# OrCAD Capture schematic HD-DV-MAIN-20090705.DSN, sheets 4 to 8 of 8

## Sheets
4 CONNECTOR: size B
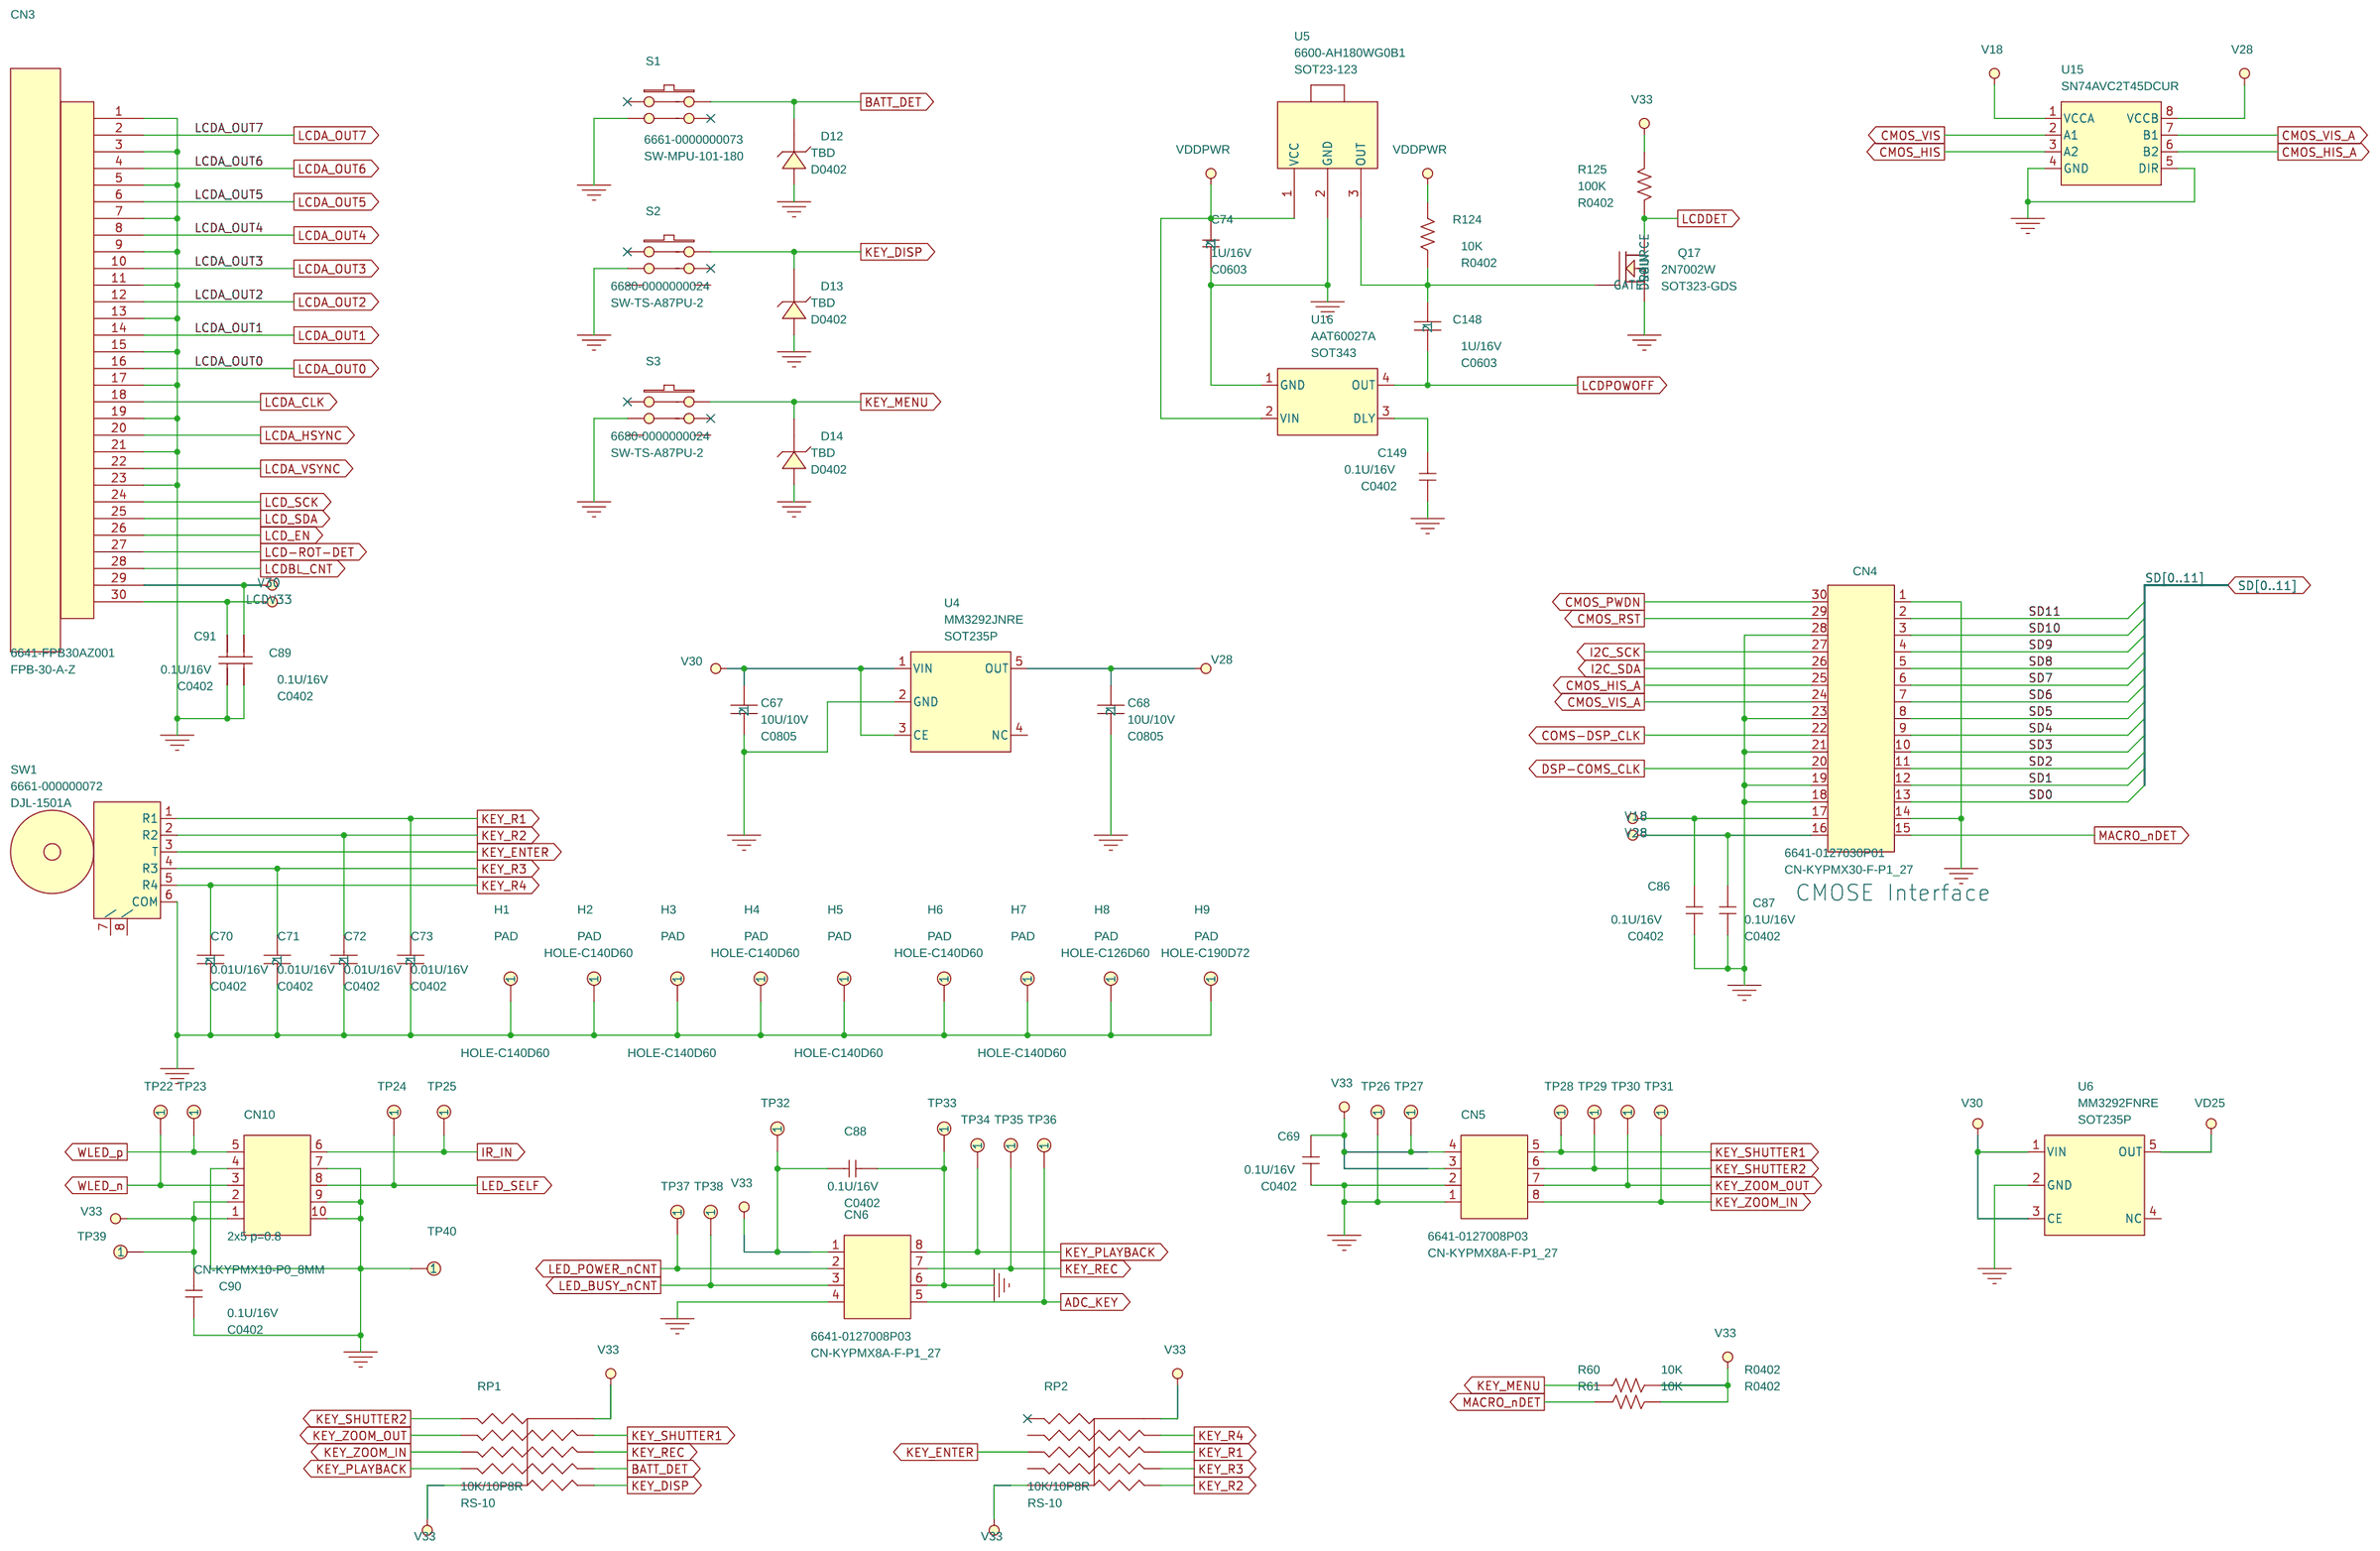
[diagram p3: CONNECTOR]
5 DDR2 SDRAM: size A4
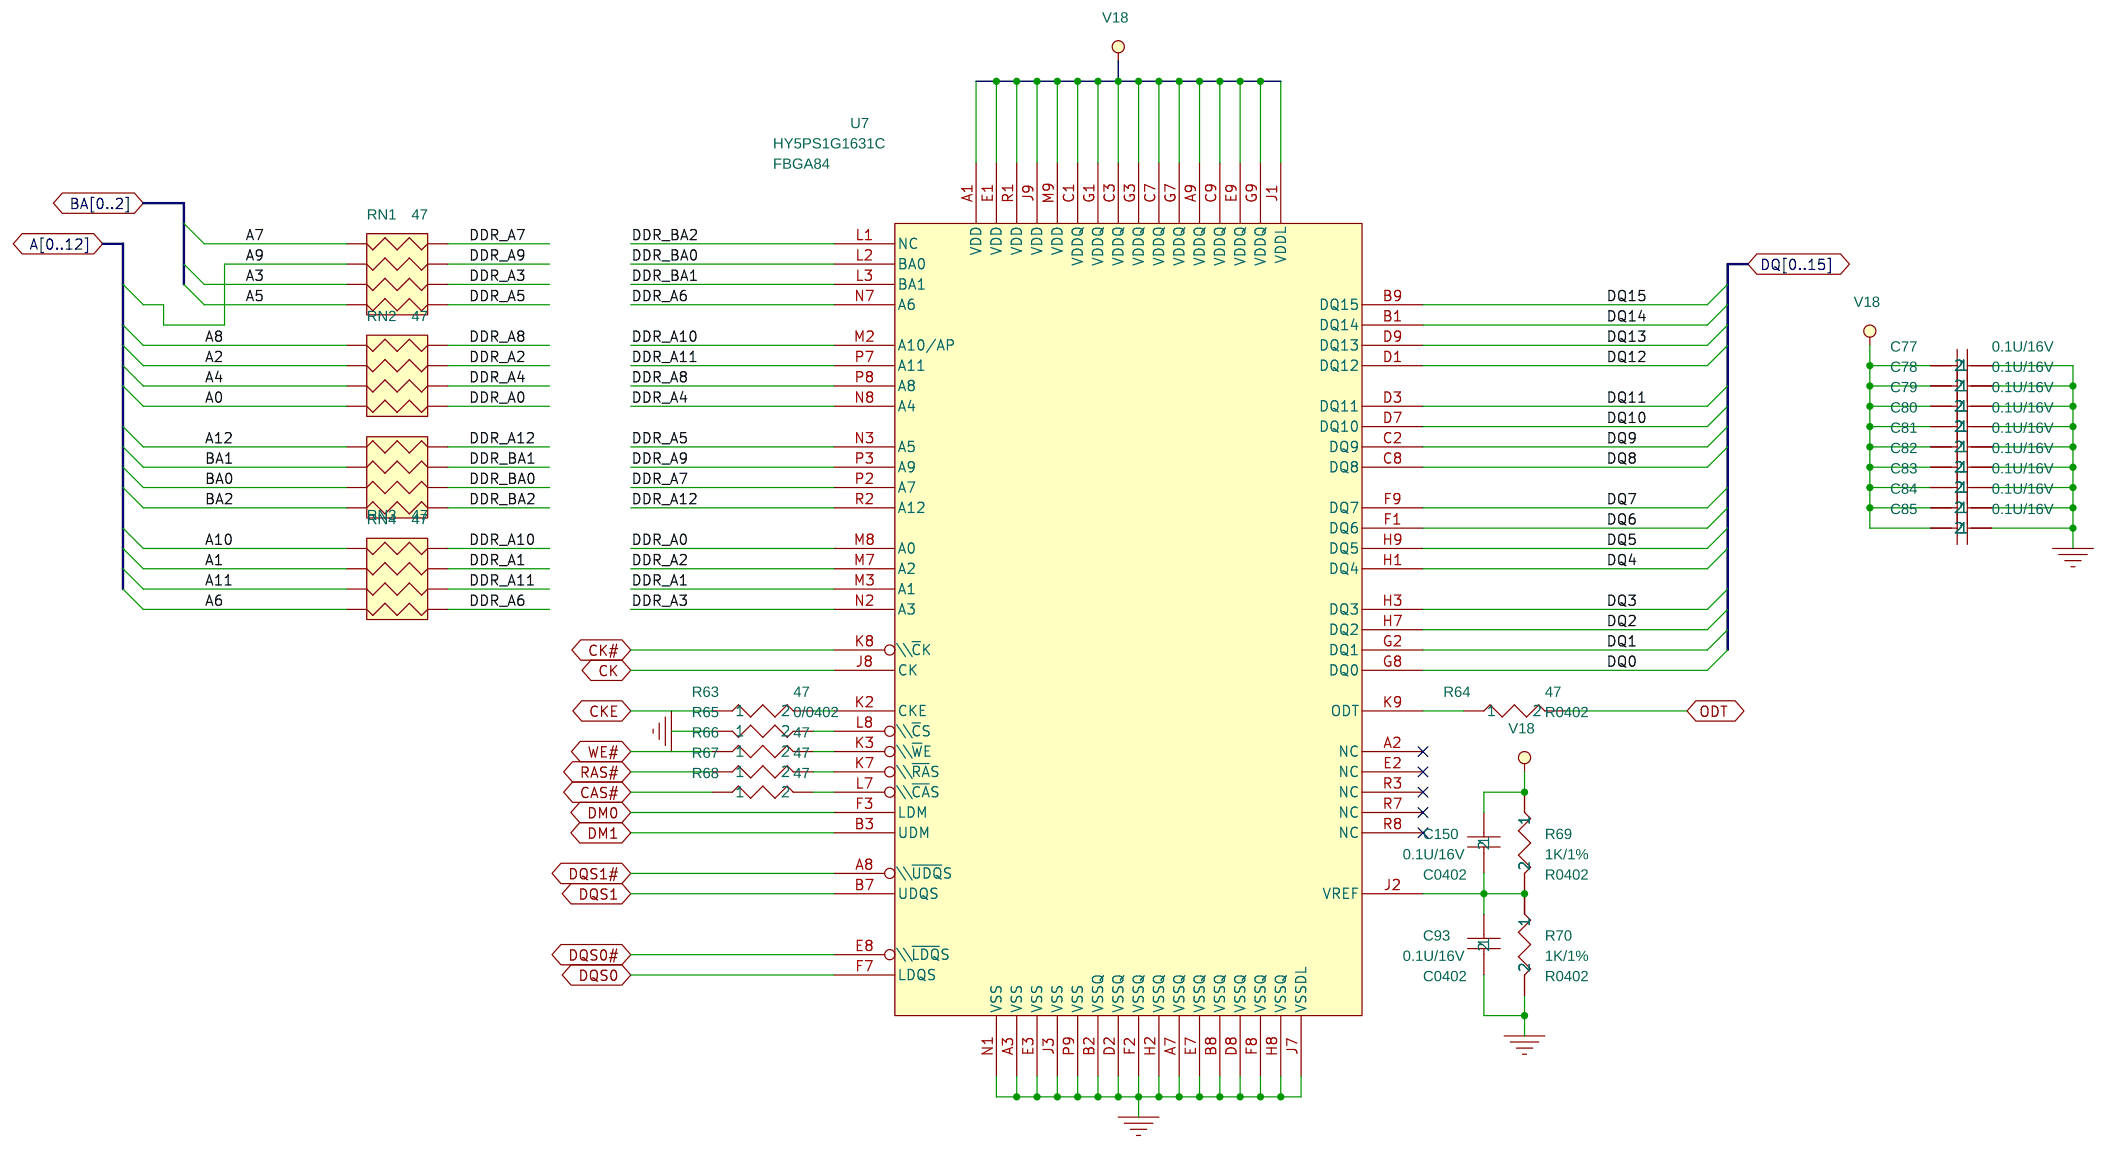
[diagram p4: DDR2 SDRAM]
6 NAND & SD: size A4
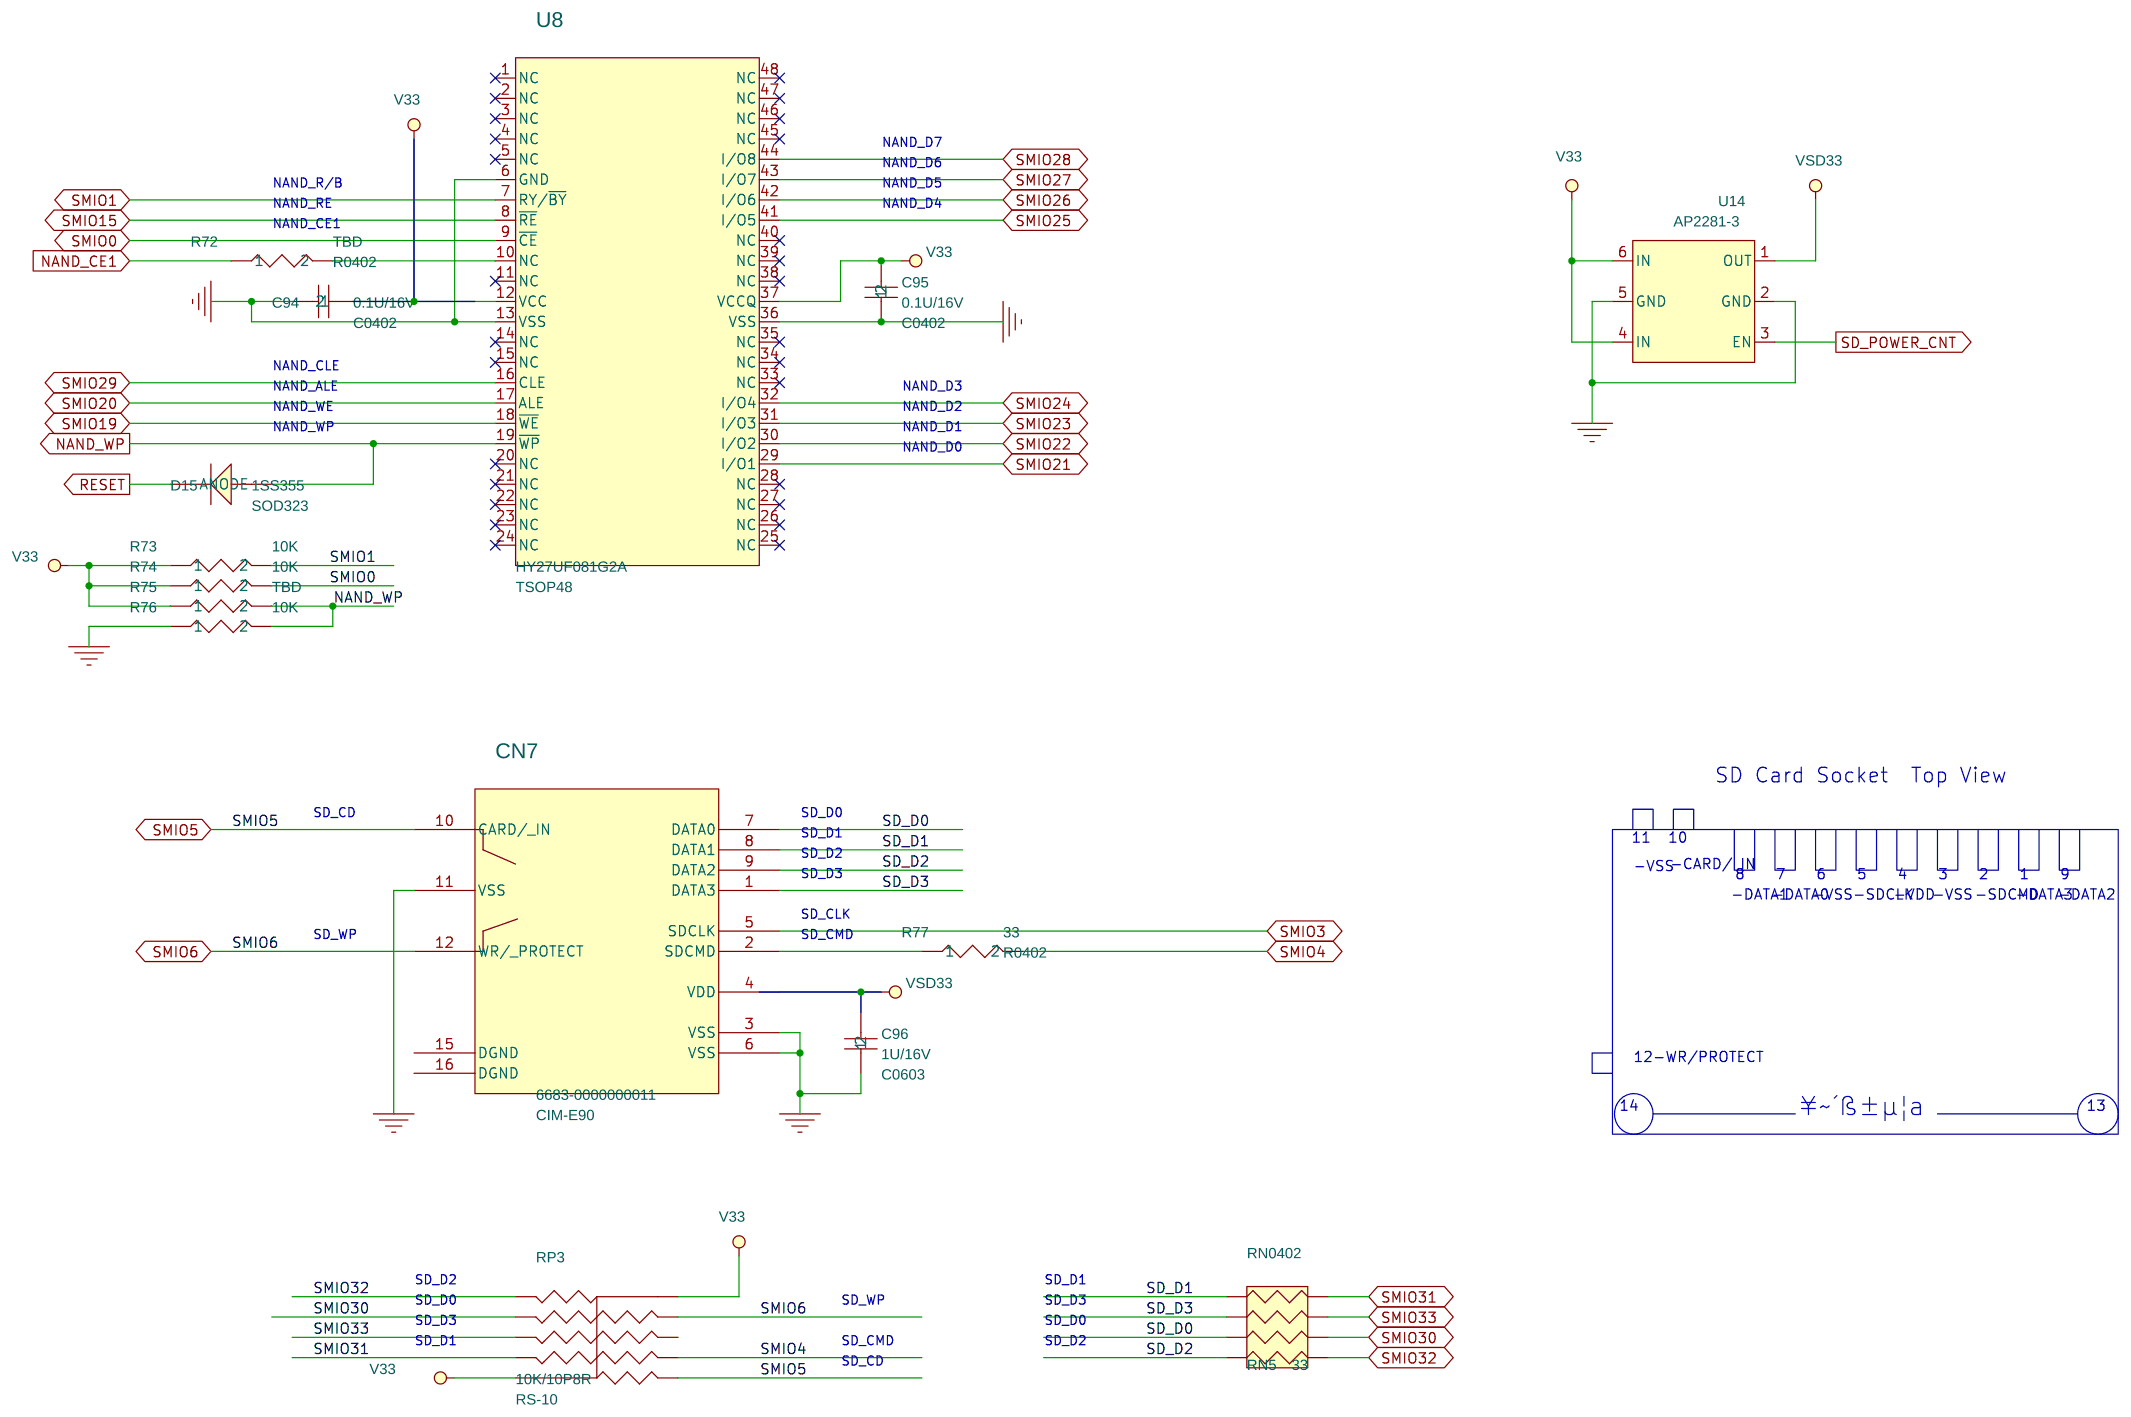
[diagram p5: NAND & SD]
7 POWER & ON & OFF: size B
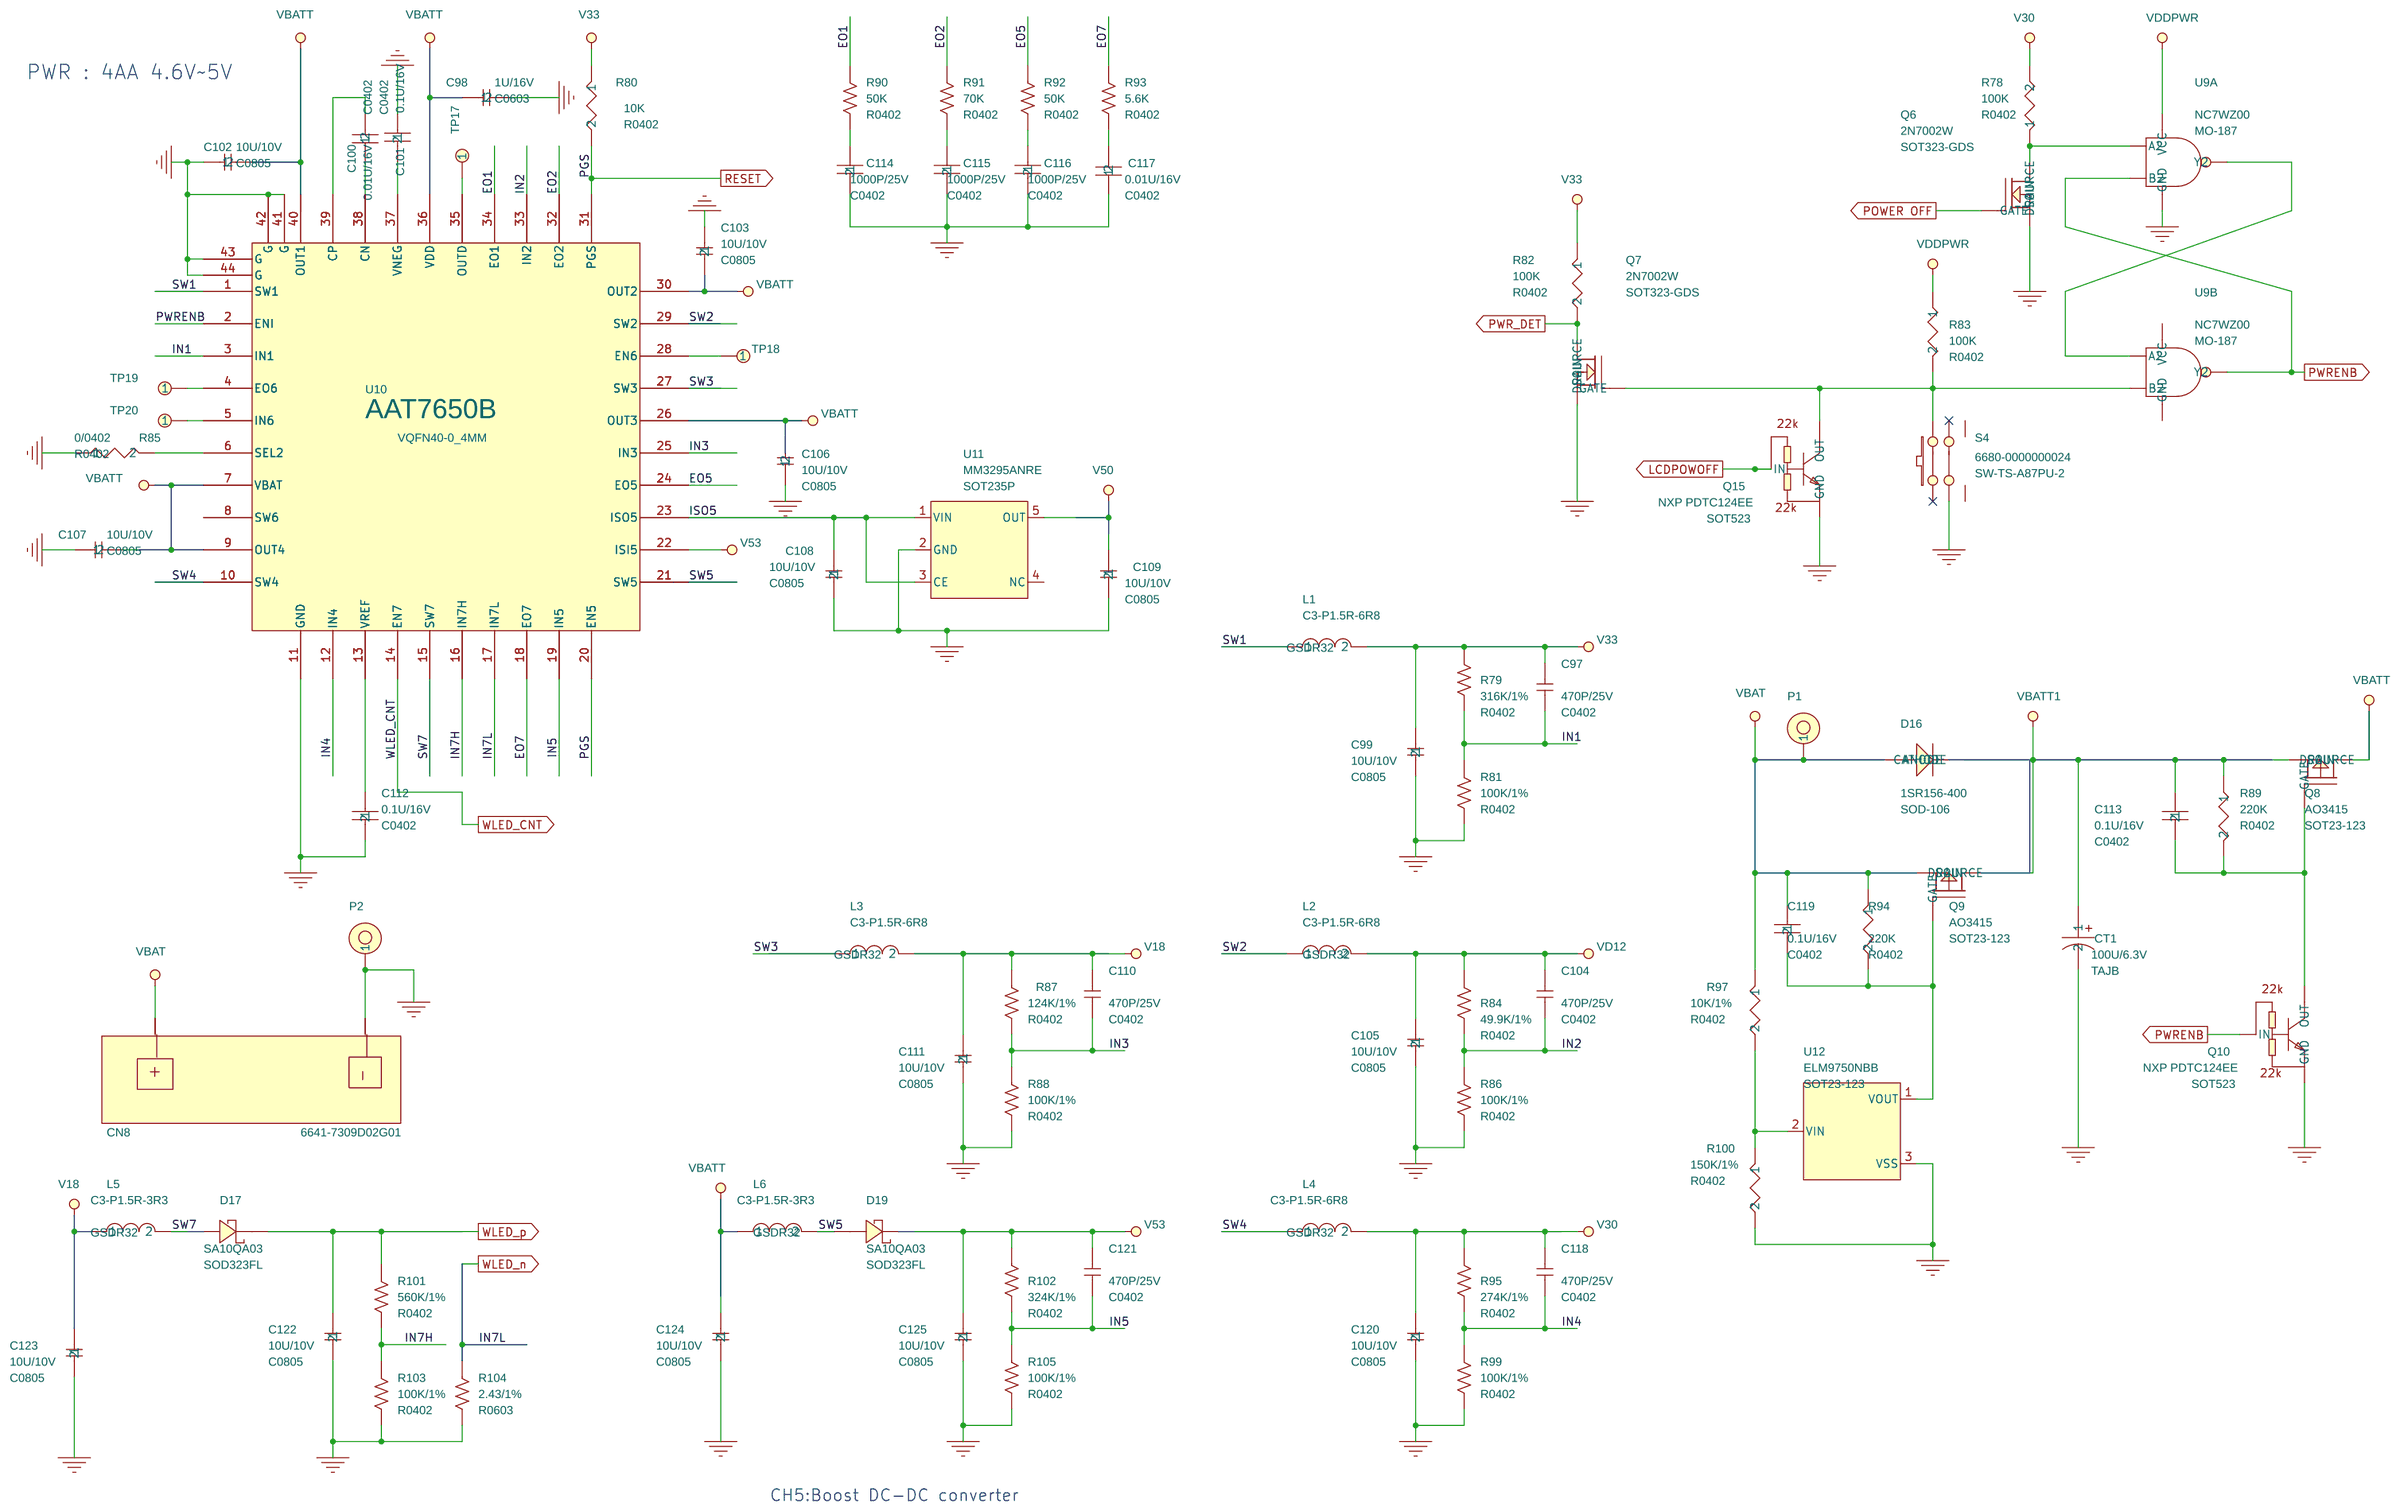
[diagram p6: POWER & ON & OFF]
8 WM8978 & USB CON: size B
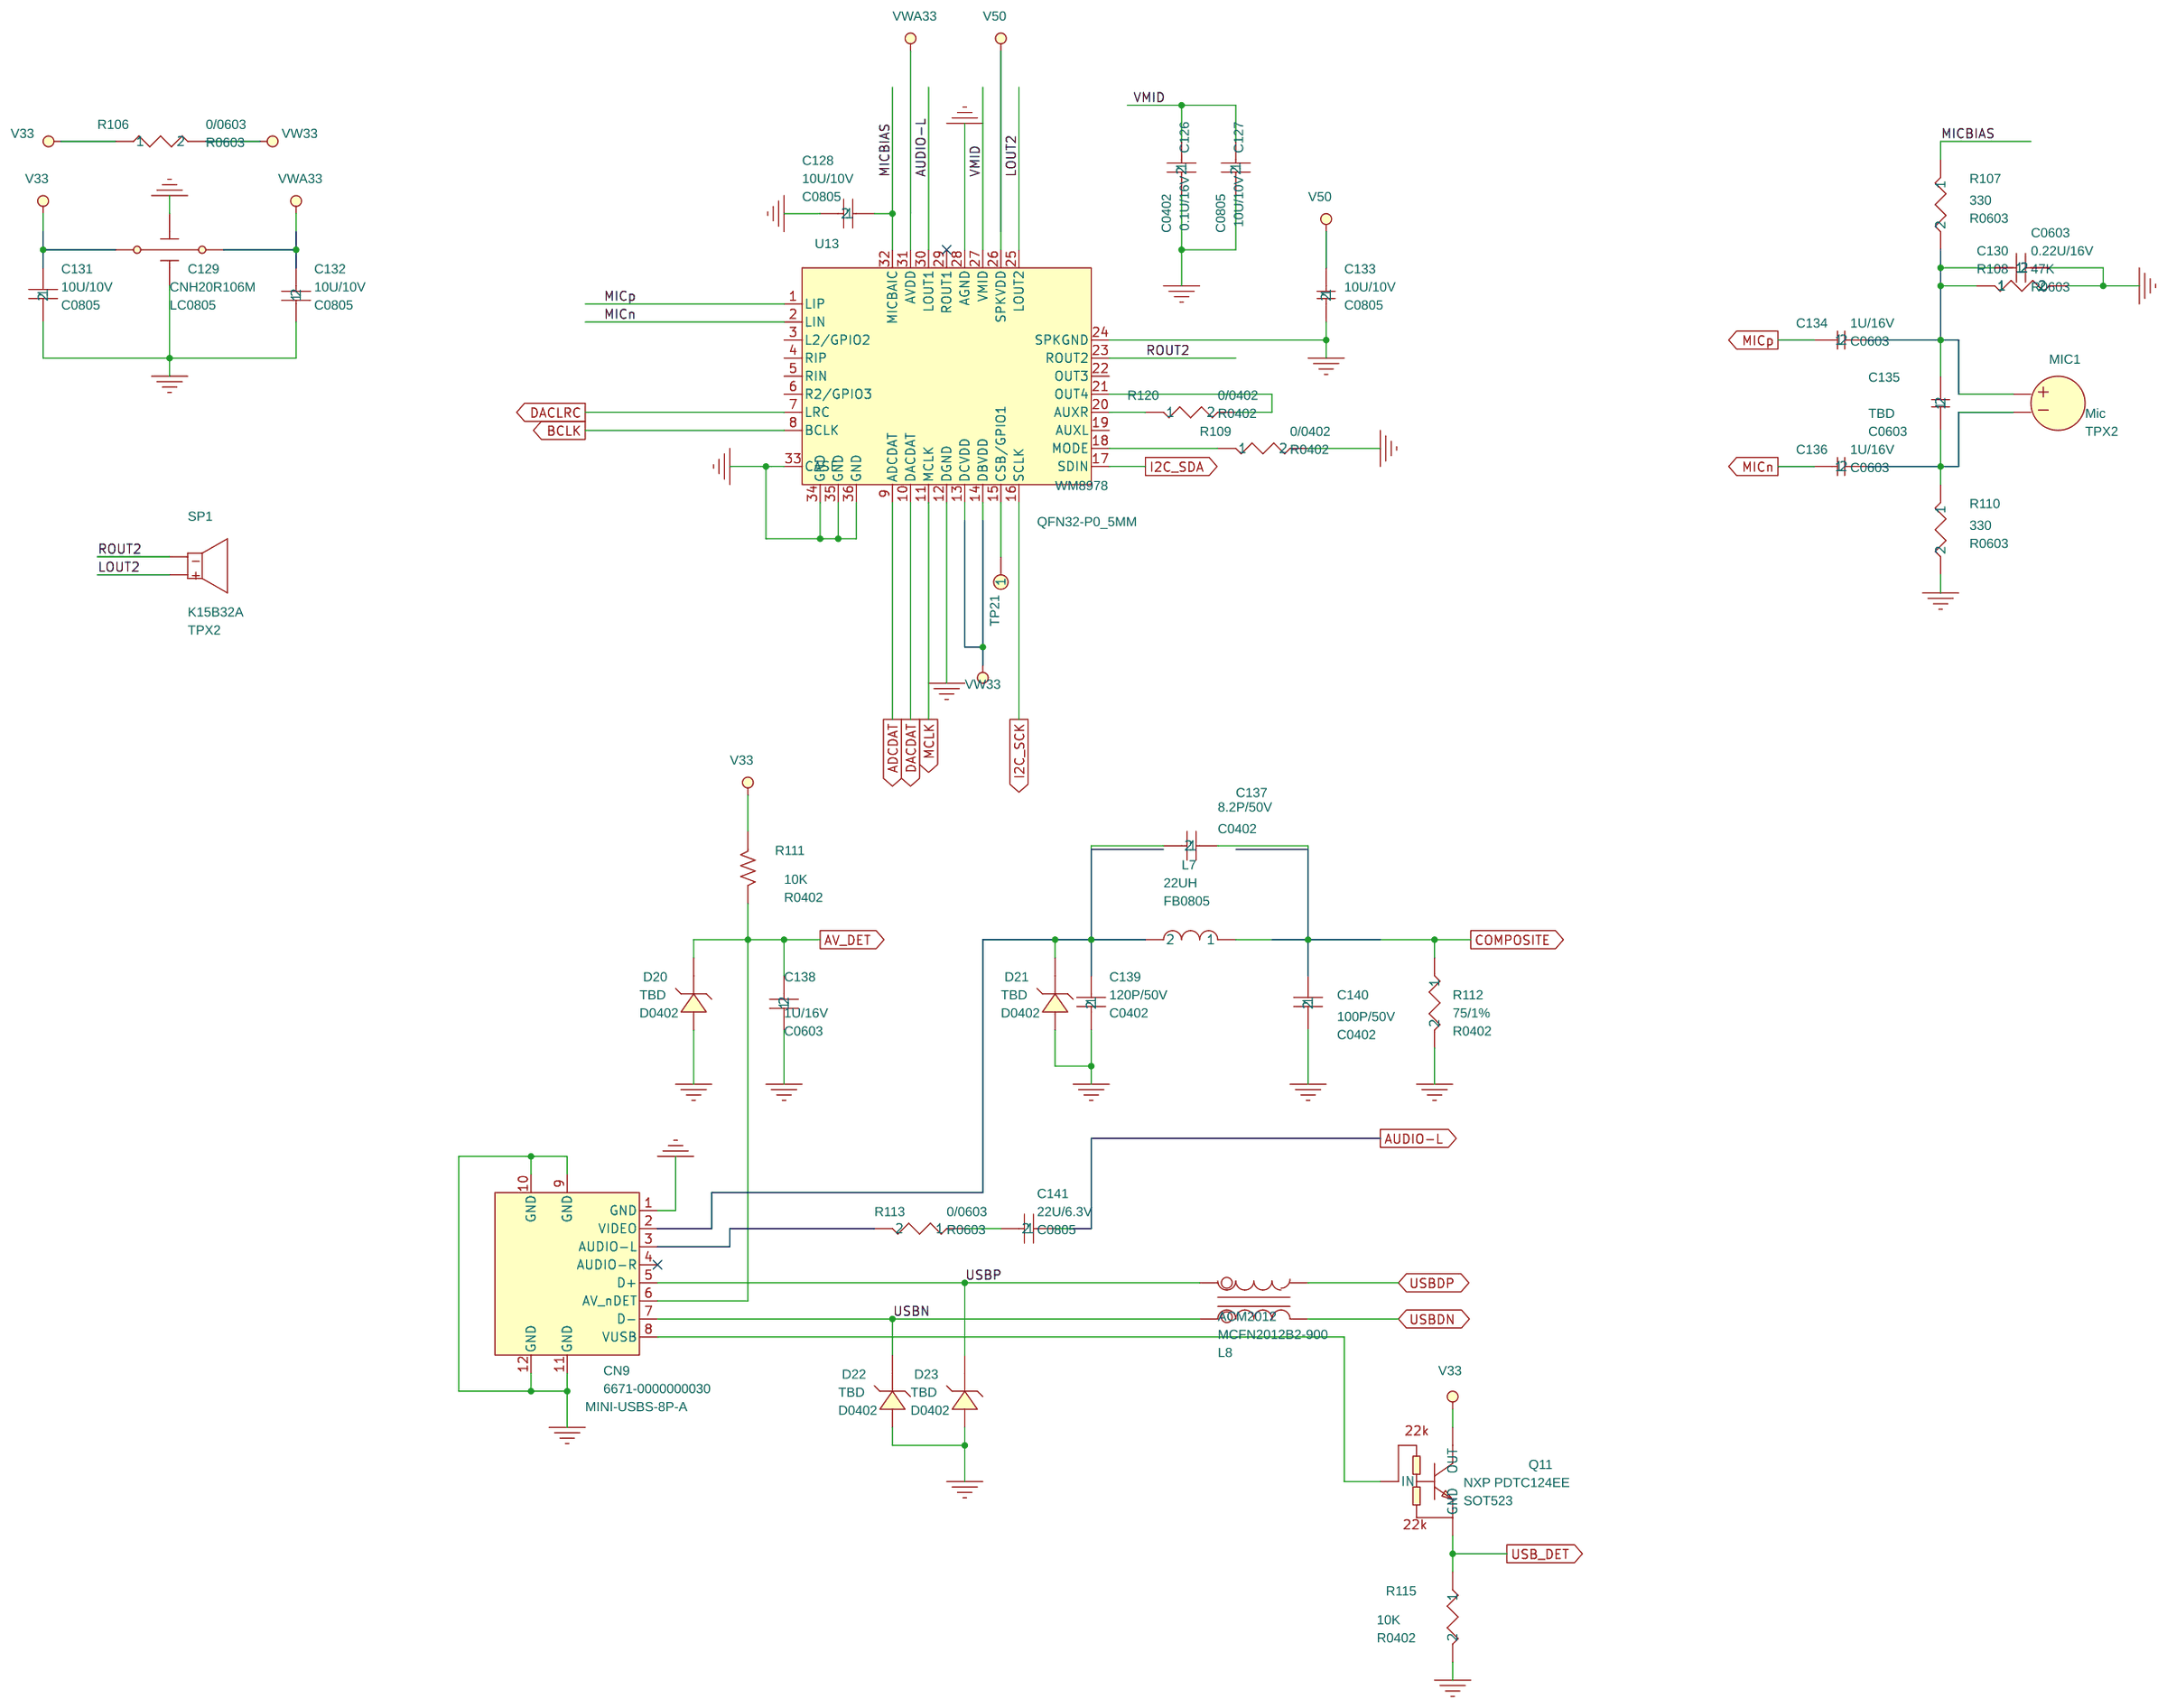
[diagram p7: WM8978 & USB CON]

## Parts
sheet CONNECTOR
C67  10U/10V  [C0805]
C68  10U/10V  [C0805]
C69  0.1U/16V  [C0402]
C70  0.01U/16V  [C0402]
C71  0.01U/16V  [C0402]
C72  0.01U/16V  [C0402]
C73  0.01U/16V  [C0402]
C74  1U/16V  [C0603]
C86  0.1U/16V  [C0402]
C87  0.1U/16V  [C0402]
C88  0.1U/16V  [C0402]
C89  0.1U/16V  [C0402]
C90  0.1U/16V  [C0402]
C91  0.1U/16V  [C0402]
C148  1U/16V  [C0603]
C149  0.1U/16V  [C0402]
CN3  6641-FPB30AZ001  [FPB-30-A-Z]
CN4  6641-0127030P01  [CN-KYPMX30-F-P1_27]
CN5  6641-0127008P03  [CN-KYPMX8A-F-P1_27]
CN6  6641-0127008P03  [CN-KYPMX8A-F-P1_27]
CN10  2x5 p=0.8  [CN-KYPMX10-P0_8MM]
D12  TBD  [D0402]
D13  TBD  [D0402]
D14  TBD  [D0402]
H1  PAD  [HOLE-C140D60]
H2  PAD  [HOLE-C140D60]
H3  PAD  [HOLE-C140D60]
H4  PAD  [HOLE-C140D60]
H5  PAD  [HOLE-C140D60]
H6  PAD  [HOLE-C140D60]
H7  PAD  [HOLE-C140D60]
H8  PAD  [HOLE-C126D60]
H9  PAD  [HOLE-C190D72]
Q17  2N7002W  [SOT323-GDS]
R60  10K  [R0402]
R61  10K  [R0402]
R124  10K  [R0402]
R125  100K  [R0402]
RP1  10K/10P8R  [RS-10]
RP2  10K/10P8R  [RS-10]
S1  6661-0000000073  [SW-MPU-101-180]
S2  6680-0000000024  [SW-TS-A87PU-2]
S3  6680-0000000024  [SW-TS-A87PU-2]
SW1  6661-000000072  [DJL-1501A]
TP22  TP  [TP40]
TP23  TP  [TP40]
TP24  TP  [TP40]
TP25  TP  [TP40]
TP26  TP  [TP40]
TP27  TP  [TP40]
TP28  TP  [TP40]
TP29  TP  [TP40]
TP30  TP  [TP40]
TP31  TP  [TP40]
TP32  TP  [TP40]
TP33  TP  [TP40]
TP34  TP  [TP40]
TP35  TP  [TP40]
TP36  TP  [TP40]
TP37  TP  [TP40]
TP38  TP  [TP40]
TP39  TP  [TP40]
TP40  TP  [TP40]
U4  MM3292JNRE  [SOT235P]
U5  6600-AH180WG0B1  [SOT23-123]
U6  MM3292FNRE  [SOT235P]
U15  SN74AVC2T45DCUR  [MO-187]
U16  AAT60027A  [SOT343]
sheet DDR2 SDRAM
C77  0.1U/16V  [C0402]
C78  0.1U/16V  [C0402]
C79  0.1U/16V  [C0402]
C80  0.1U/16V  [C0402]
C81  0.1U/16V  [C0402]
C82  0.1U/16V  [C0402]
C83  0.1U/16V  [C0402]
C84  0.1U/16V  [C0402]
C85  0.1U/16V  [C0402]
C93  0.1U/16V  [C0402]
C150  0.1U/16V  [C0402]
R63  47  [R0402]
R64  47  [R0402]
R65  0/0402  [R0402]
R66  47  [R0402]
R67  47  [R0402]
R68  47  [R0402]
R69  1K/1%  [R0402]
R70  1K/1%  [R0402]
RN1  47  [RN0402]
RN2  47  [RN0402]
RN3  47  [RN0402]
RN4  47  [RN0402]
U7  HY5PS1G1631C  [FBGA84]
sheet NAND & SD
C94  0.1U/16V  [C0402]
C95  0.1U/16V  [C0402]
C96  1U/16V  [C0603]
CN7  6683-0000000011  [CIM-E90]
D15  1SS355  [SOD323]
R72  TBD  [R0402]
R73  10K  [R0402]
R74  10K  [R0402]
R75  TBD  [R0402]
R76  10K  [R0402]
R77  33  [R0402]
RN5  33  [RN0402]
RP3  10K/10P8R  [RS-10]
U8  HY27UF081G2A  [TSOP48]
U14  AP2281-3  [SOT26]
sheet POWER & ON & OFF
C97  470P/25V  [C0402]
C98  1U/16V  [C0603]
C99  10U/10V  [C0805]
C100  0.01U/16V  [C0402]
C101  0.1U/16V  [C0402]
C102  10U/10V  [C0805]
C103  10U/10V  [C0805]
C104  470P/25V  [C0402]
C105  10U/10V  [C0805]
C106  10U/10V  [C0805]
C107  10U/10V  [C0805]
C108  10U/10V  [C0805]
C109  10U/10V  [C0805]
C110  470P/25V  [C0402]
C111  10U/10V  [C0805]
C112  0.1U/16V  [C0402]
C113  0.1U/16V  [C0402]
C114  1000P/25V  [C0402]
C115  1000P/25V  [C0402]
C116  1000P/25V  [C0402]
C117  0.01U/16V  [C0402]
C118  470P/25V  [C0402]
C119  0.1U/16V  [C0402]
C120  10U/10V  [C0805]
C121  470P/25V  [C0402]
C122  10U/10V  [C0805]
C123  10U/10V  [C0805]
C124  10U/10V  [C0805]
C125  10U/10V  [C0805]
CN8  6641-7309D02G01  [bat-7309d-02g-003]
CT1  100U/6.3V  [TAJB]
D16  1SR156-400  [SOD-106]
D17  SA10QA03  [SOD323FL]
D19  SA10QA03  [SOD323FL]
L1  C3-P1.5R-6R8  [GSDR32]
L2  C3-P1.5R-6R8  [GSDR32]
L3  C3-P1.5R-6R8  [GSDR32]
L4  C3-P1.5R-6R8  [GSDR32]
L5  C3-P1.5R-3R3  [GSDR32]
L6  C3-P1.5R-3R3  [GSDR32]
P1  TP  [HOLE-C80D40]
P2  TP  [HOLE-C80D40]
Q6  2N7002W  [SOT323-GDS]
Q7  2N7002W  [SOT323-GDS]
Q8  AO3415  [SOT23-123]
Q9  AO3415  [SOT23-123]
Q10  NXP PDTC124EE  [SOT523]
Q15  NXP PDTC124EE  [SOT523]
R78  100K  [R0402]
R79  316K/1%  [R0402]
R80  10K  [R0402]
R81  100K/1%  [R0402]
R82  100K  [R0402]
R83  100K  [R0402]
R84  49.9K/1%  [R0402]
R85  0/0402  [R0402]
R86  100K/1%  [R0402]
R87  124K/1%  [R0402]
R88  100K/1%  [R0402]
R89  220K  [R0402]
R90  50K  [R0402]
R91  70K  [R0402]
R92  50K  [R0402]
R93  5.6K  [R0402]
R94  220K  [R0402]
R95  274K/1%  [R0402]
R97  10K/1%  [R0402]
R99  100K/1%  [R0402]
R100  150K/1%  [R0402]
R101  560K/1%  [R0402]
R102  324K/1%  [R0402]
R103  100K/1%  [R0402]
R104  2.43/1%  [R0603]
R105  100K/1%  [R0402]
S4  6680-0000000024  [SW-TS-A87PU-2]
TP17  TP  [TP30]
TP18  TP  [TP30]
TP19  TP  [TP30]
TP20  TP  [TP30]
U9  NC7WZ00  [MO-187]  (sections A,B)
U10  AAT7650B  [VQFN40-0_4MM]
U11  MM3295ANRE  [SOT235P]
U12  ELM9750NBB  [SOT23-123]
sheet WM8978 & USB CON
C126  0.1U/16V  [C0402]
C127  10U/10V  [C0805]
C128  10U/10V  [C0805]
C129  CNH20R106M  [LC0805]
C130  0.22U/16V  [C0603]
C131  10U/10V  [C0805]
C132  10U/10V  [C0805]
C133  10U/10V  [C0805]
C134  1U/16V  [C0603]
C135  TBD  [C0603]
C136  1U/16V  [C0603]
C137  8.2P/50V  [C0402]
C138  1U/16V  [C0603]
C139  120P/50V  [C0402]
C140  100P/50V  [C0402]
C141  22U/6.3V  [C0805]
CN9  6671-0000000030  [MINI-USBS-8P-A]
D20  TBD  [D0402]
D21  TBD  [D0402]
D22  TBD  [D0402]
D23  TBD  [D0402]
L7  22UH  [FB0805]
L8  MCFN2012B2-900  [ACM2012]
MIC1  Mic  [TPX2]
Q11  NXP PDTC124EE  [SOT523]
R106  0/0603  [R0603]
R107  330  [R0603]
R108  47K  [R0603]
R109  0/0402  [R0402]
R110  330  [R0603]
R111  10K  [R0402]
R112  75/1%  [R0402]
R113  0/0603  [R0603]
R115  10K  [R0402]
R120  0/0402  [R0402]
SP1  K15B32A  [TPX2]
TP21  TP  [TP30]
U13  WM8978  [QFN32-P0_5MM]

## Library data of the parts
C67 = CAP_NP_4: CHIP CAP,106PK/10V,0805,X5R; Approved: Y; BOM Value: 10U/10V/X5R/0805; CIS_PART_NUMBER: 24-3A5-10606-000-TAIYO YUDEN; Manufacturer: TAIYO YUDEN; Manufacturer's Part Number: LMK212BJ106KG; Material: X5R; PART_TYPE: MLCC; Package Type: 0805; Part Number: 24-3A5-10606-000; Rate Volt: 10V; Tolerance: 10%
C68 = CAP_NP_5: CHIP CAP,106PK/10V,0805,X5R; Approved: Y; BOM Value: 10U/10V/X5R/0805; CIS_PART_NUMBER: 24-3A5-10606-000-TAIYO YUDEN; Manufacturer: TAIYO YUDEN; Manufacturer's Part Number: LMK212BJ106KG; Material: X5R; PART_TYPE: MLCC; Package Type: 0805; Part Number: 24-3A5-10606-000; Rate Volt: 10V; Tolerance: 10%
C69 C86-C91 C149 = C: BOM Value: 0.1U/16V/X5R/0402
C70 = CAP_NP_3: CHIP CAP,104PZ/16V,0402,Y5V; Approved: Y; BOM Value: 0.01U/16V/X5R/0402; CIS_PART_NUMBER: 24-3E3-10418-000-POE; Manufacturer: POE; Manufacturer's Part Number: B0402F104ZCT; Material: Y5V; PART_TYPE: MLCC; Package Type: 0402; Part Number: 24-3E3-10418-000; Rate Volt: 16V; Tolerance: -20~+80
C71 C100 = CAP_NP: CHIP CAP,104PZ/16V,0402,Y5V; Approved: Y; BOM Value: 0.01U/16V/X5R/0402; CIS_PART_NUMBER: 24-3E3-10418-000-POE; Manufacturer: POE; Manufacturer's Part Number: B0402F104ZCT; Material: Y5V; PART_TYPE: MLCC; Package Type: 0402; Part Number: 24-3E3-10418-000; Rate Volt: 16V; Tolerance: -20~+80
C72 = CAP_NP_1: CHIP CAP,104PZ/16V,0402,Y5V; Approved: Y; BOM Value: 0.01U/16V/X5R/0402; CIS_PART_NUMBER: 24-3E3-10418-000-POE; Manufacturer: POE; Manufacturer's Part Number: B0402F104ZCT; Material: Y5V; PART_TYPE: MLCC; Package Type: 0402; Part Number: 24-3E3-10418-000; Rate Volt: 16V; Tolerance: -20~+80
C73 = CAP_NP_2: CHIP CAP,104PZ/16V,0402,Y5V; Approved: Y; BOM Value: 0.01U/16V/X5R/0402; CIS_PART_NUMBER: 24-3E3-10418-000-POE; Manufacturer: POE; Manufacturer's Part Number: B0402F104ZCT; Material: Y5V; PART_TYPE: MLCC; Package Type: 0402; Part Number: 24-3E3-10418-000; Rate Volt: 16V; Tolerance: -20~+80
C74 C134 = CAP_CERAMIC_0: BOM Value: 1U/16V/X5R/0603
C148 = CAP_NP_6: CHIP CAP,105PZ/6.3V,0402,Y5V; Approved: Y; BOM Value: 1U/16V/X5R/0603; CIS_PART_NUMBER: 24-3E3-105G8-000-POE; Manufacturer: POE; Manufacturer's Part Number: K0402F105ZCT; Material: Y5V; PART_TYPE: MLCC; Package Type: 0402; Part Number: 24-3E3-105G8-000; Rate Volt: 6.3V; Tolerance: -20~+80
CN3 = FPC_CON24P_0: Vender: ®¦±o§Q
CN4 = CON10_5: Vender: ´Wµ¾
CN5 = CON10_1: Vender: «Å±o
CN6 = CON10_4: Vender: «Å±o
CN10 = CON10_7: Vender: «Å±o
D12-D14 D20-D23 = DIODE_ZENER_0: Vender: PHILIPS
H1-H9 = POINT_2
Q6 Q7 Q17 = MOSFET_N_2
R60 = R_1: BOM Value: 10K/5%/0402
R61 R111 = R: BOM Value: 10K/5%/0402
R124 = R_2: BOM Value: 10K/5%/0402
R125 = R_3: BOM Value: 100K/5%/0402
RP1-RP3 = 10P8R: BOM Value: 10K/5%/10P8R
S1 = SKHHAJ_3: Push Button SMD; Manufacture: ´¹¨¹; Package: SMD 8.5mmx5mm; Vender: ´¹¨¹
S2-S4 = SKHHAJ_2: Push Button SMD; Manufacture: ´¹¨¹; Package: SMD 8.5mmx5mm; Vender: ´¹¨¹
SW1 = CON10_6: Vender: «Ò¾W
TP17-TP40 = POINT_2: 8TH PART FIELD: PADR60
U4 U6 U11 = AT1202_3
U5 = RX5RL_3: Vender: ANACHIP
U15 = AT1202_7
U16 = AT1202_4
C77 C101 = CAP_NP_8: CHIP CAP,104PZ/16V,0402,Y5V; Approved: Y; BOM Value: 0.1U/16V/X5R/0402; CIS_PART_NUMBER: 24-3E3-10418-000-POE; Manufacturer: POE; Manufacturer's Part Number: B0402F104ZCT; Material: Y5V; PART_TYPE: MLCC; Package Type: 0402; Part Number: 24-3E3-10418-000; Rate Volt: 16V; Tolerance: -20~+80
C78 = CAP_NP_10: CHIP CAP,104PZ/16V,0402,Y5V; Approved: Y; BOM Value: 0.1U/16V/X5R/0402; CIS_PART_NUMBER: 24-3E3-10418-000-POE; Manufacturer: POE; Manufacturer's Part Number: B0402F104ZCT; Material: Y5V; PART_TYPE: MLCC; Package Type: 0402; Part Number: 24-3E3-10418-000; Rate Volt: 16V; Tolerance: -20~+80
C79 C112 = CAP_NP_6: CHIP CAP,104PZ/16V,0402,Y5V; Approved: Y; BOM Value: 0.1U/16V/X5R/0402; CIS_PART_NUMBER: 24-3E3-10418-000-POE; Manufacturer: POE; Manufacturer's Part Number: B0402F104ZCT; Material: Y5V; PART_TYPE: MLCC; Package Type: 0402; Part Number: 24-3E3-10418-000; Rate Volt: 16V; Tolerance: -20~+80
C80 = CAP_NP_3: CHIP CAP,104PZ/16V,0402,Y5V; Approved: Y; BOM Value: 0.1U/16V/X5R/0402; CIS_PART_NUMBER: 24-3E3-10418-000-POE; Manufacturer: POE; Manufacturer's Part Number: B0402F104ZCT; Material: Y5V; PART_TYPE: MLCC; Package Type: 0402; Part Number: 24-3E3-10418-000; Rate Volt: 16V; Tolerance: -20~+80
C81 = CAP_NP_4: CHIP CAP,104PZ/16V,0402,Y5V; Approved: Y; BOM Value: 0.1U/16V/X5R/0402; CIS_PART_NUMBER: 24-3E3-10418-000-POE; Manufacturer: POE; Manufacturer's Part Number: B0402F104ZCT; Material: Y5V; PART_TYPE: MLCC; Package Type: 0402; Part Number: 24-3E3-10418-000; Rate Volt: 16V; Tolerance: -20~+80
C82 = CAP_NP_5: CHIP CAP,104PZ/16V,0402,Y5V; Approved: Y; BOM Value: 0.1U/16V/X5R/0402; CIS_PART_NUMBER: 24-3E3-10418-000-POE; Manufacturer: POE; Manufacturer's Part Number: B0402F104ZCT; Material: Y5V; PART_TYPE: MLCC; Package Type: 0402; Part Number: 24-3E3-10418-000; Rate Volt: 16V; Tolerance: -20~+80
C83 = CAP_NP_7: CHIP CAP,104PZ/16V,0402,Y5V; Approved: Y; BOM Value: 0.1U/16V/X5R/0402; CIS_PART_NUMBER: 24-3E3-10418-000-POE; Manufacturer: POE; Manufacturer's Part Number: B0402F104ZCT; Material: Y5V; PART_TYPE: MLCC; Package Type: 0402; Part Number: 24-3E3-10418-000; Rate Volt: 16V; Tolerance: -20~+80
C84 C95 = CAP_NP: CHIP CAP,104PZ/16V,0402,Y5V; Approved: Y; BOM Value: 0.1U/16V/X5R/0402; CIS_PART_NUMBER: 24-3E3-10418-000-POE; Manufacturer: POE; Manufacturer's Part Number: B0402F104ZCT; Material: Y5V; PART_TYPE: MLCC; Package Type: 0402; Part Number: 24-3E3-10418-000; Rate Volt: 16V; Tolerance: -20~+80
C85 = CAP_NP_2: CHIP CAP,104PZ/16V,0402,Y5V; Approved: Y; BOM Value: 0.1U/16V/X5R/0402; CIS_PART_NUMBER: 24-3E3-10418-000-POE; Manufacturer: POE; Manufacturer's Part Number: B0402F104ZCT; Material: Y5V; PART_TYPE: MLCC; Package Type: 0402; Part Number: 24-3E3-10418-000; Rate Volt: 16V; Tolerance: -20~+80
C93 C94 C119 = CAP_NP_1: CHIP CAP,104PZ/16V,0402,Y5V; Approved: Y; BOM Value: 0.1U/16V/X5R/0402; CIS_PART_NUMBER: 24-3E3-10418-000-POE; Manufacturer: POE; Manufacturer's Part Number: B0402F104ZCT; Material: Y5V; PART_TYPE: MLCC; Package Type: 0402; Part Number: 24-3E3-10418-000; Rate Volt: 16V; Tolerance: -20~+80
C150 = CAP_NP_9: CHIP CAP,104PZ/16V,0402,Y5V; Approved: Y; BOM Value: 0.1U/16V/X5R/0402; CIS_PART_NUMBER: 24-3E3-10418-000-POE; Manufacturer: POE; Manufacturer's Part Number: B0402F104ZCT; Material: Y5V; PART_TYPE: MLCC; Package Type: 0402; Part Number: 24-3E3-10418-000; Rate Volt: 16V; Tolerance: -20~+80
R63 = R_v2_7: CHIP RES,22ohm,0402 J; BOM Value: 47/5%/0402; CIS_PART_NUMBER: 20-116-22006-µØ·s; Manufacturer: µØ·s; Manufacturer's Part Number: 22ohm; PART_TYPE: CHIP RES; Package Type: 0402; Part Number: 20-116-22006; Tolerance: 5%; W: 1/16w
R64 = R_v2_4: CHIP RES,22ohm,0402 J; BOM Value: 47/5%/0402; CIS_PART_NUMBER: 20-116-22006-µØ·s; Manufacturer: µØ·s; Manufacturer's Part Number: 22ohm; PART_TYPE: CHIP RES; Package Type: 0402; Part Number: 20-116-22006; Tolerance: 5%; W: 1/16w
R65 = R_v2_3: CHIP RES,1K,0402 F; Approved: Y; BOM Value: 0/5%/0402; CIS_PART_NUMBER: 20-266-10010-000-RALEC; Manufacturer: RALEC; Manufacturer's Part Number: RTT021001FTP; PART_TYPE: CHIP RES; Package Type: 0402; Part Number: 20-266-10010-000; Tolerance: 1%; W: 1/16W
R66 = R_v2_2: CHIP RES,22ohm,0402 J; BOM Value: 47/5%/0402; CIS_PART_NUMBER: 20-116-22006-µØ·s; Manufacturer: µØ·s; Manufacturer's Part Number: 22ohm; PART_TYPE: CHIP RES; Package Type: 0402; Part Number: 20-116-22006; Tolerance: 5%; W: 1/16w
R67 = R_v2_6: CHIP RES,22ohm,0402 J; BOM Value: 47/5%/0402; CIS_PART_NUMBER: 20-116-22006-µØ·s; Manufacturer: µØ·s; Manufacturer's Part Number: 22ohm; PART_TYPE: CHIP RES; Package Type: 0402; Part Number: 20-116-22006; Tolerance: 5%; W: 1/16w
R68 = R_v2: CHIP RES,22ohm,0402 J; BOM Value: 47/5%/0402; CIS_PART_NUMBER: 20-116-22006-µØ·s; Manufacturer: µØ·s; Manufacturer's Part Number: 22ohm; PART_TYPE: CHIP RES; Package Type: 0402; Part Number: 20-116-22006; Tolerance: 5%; W: 1/16w
R69 = R_v2_5: CHIP RES,1K,0402 F; Approved: Y; BOM Value: 1K/1%/0402; CIS_PART_NUMBER: 20-266-10010-000-RALEC; Manufacturer: RALEC; Manufacturer's Part Number: RTT021001FTP; PART_TYPE: CHIP RES; Package Type: 0402; Part Number: 20-266-10010-000; Tolerance: 1%; W: 1/16W
R70 = R_v2_1: CHIP RES,1K,0402 F; Approved: Y; BOM Value: 1K/1%/0402; CIS_PART_NUMBER: 20-266-10010-000-RALEC; Manufacturer: RALEC; Manufacturer's Part Number: RTT021001FTP; PART_TYPE: CHIP RES; Package Type: 0402; Part Number: 20-266-10010-000; Tolerance: 1%; W: 1/16W
RN1-RN4 = R_PAK_4: BOM Value: 47/8P4R/0402
U7 = K4T51163QC-ZCD5_0: DDR2 SDRAM 32MBx16DDR2-533,FBGA84,SAMSUNG; Approved: Y; CIS_PART_NUMBER: 08-109-00002-000-SAMSUNG; Index1: VDD=1.7V~1.9V; Index3: 533MHz; Manufacturer: SAMSUNG; Manufacturer's Part Number: K4T51163QC-ZCD5; PART_TYPE: DDR; Package Type: FBGA 84; Part Number: 08-109-00002-000; Size: 32M*16
C96 = CAP_NP_2: CHIP CAP,105PZ/6.3V,0402,Y5V; Approved: Y; BOM Value: 1U/16V/X5R/0603; CIS_PART_NUMBER: 24-3E3-105G8-000-POE; Manufacturer: POE; Manufacturer's Part Number: K0402F105ZCT; Material: Y5V; PART_TYPE: MLCC; Package Type: 0402; Part Number: 24-3E3-105G8-000; Rate Volt: 6.3V; Tolerance: -20~+80
CN7 = SD_SOCKET12_0: SD SOCKET,12P,H4.6mm,SMD; Approved: Y; CIS_PART_NUMBER: 40-140-12002-000-MITSUMI; Manufacturer: MITSUMI; Manufacturer's Part Number: CIM-E90 R41-2471C; PART_TYPE: SOCKET; Package Type: SMD; Part Number: 40-140-12002-000; Pitch_Pin No.: 12P; Rating Current: 0.5A
D15 = DIODE_0
R72 = R_v2_1: CHIP RES,10K,0402 J; Approved: Y; CIS_PART_NUMBER: 20-116-10306-000-RALEC; Manufacturer: RALEC; Manufacturer's Part Number: RTT02103JTP; PART_TYPE: CHIP RES; Package Type: 0402; Part Number: 20-116-10306-000; Tolerance: 5%; W: 1/16W
R73 = R_v2_4: CHIP RES,10K,0402 J; Approved: Y; BOM Value: 10K/5%/0402; CIS_PART_NUMBER: 20-116-10306-000-RALEC; Manufacturer: RALEC; Manufacturer's Part Number: RTT02103JTP; PART_TYPE: CHIP RES; Package Type: 0402; Part Number: 20-116-10306-000; Tolerance: 5%; W: 1/16W
R74 = R_v2_2: CHIP RES,10K,0402 J; Approved: Y; BOM Value: 10K/5%/0402; CIS_PART_NUMBER: 20-116-10306-000-RALEC; Manufacturer: RALEC; Manufacturer's Part Number: RTT02103JTP; PART_TYPE: CHIP RES; Package Type: 0402; Part Number: 20-116-10306-000; Tolerance: 5%; W: 1/16W
R75 = R_v2_3: CHIP RES,10K,0402 J; Approved: Y; CIS_PART_NUMBER: 20-116-10306-000-RALEC; Manufacturer: RALEC; Manufacturer's Part Number: RTT02103JTP; PART_TYPE: CHIP RES; Package Type: 0402; Part Number: 20-116-10306-000; Tolerance: 5%; W: 1/16W
R76 = R_v2: CHIP RES,10K,0402 J; Approved: Y; BOM Value: 10K/5%/0402; CIS_PART_NUMBER: 20-116-10306-000-RALEC; Manufacturer: RALEC; Manufacturer's Part Number: RTT02103JTP; PART_TYPE: CHIP RES; Package Type: 0402; Part Number: 20-116-10306-000; Tolerance: 5%; W: 1/16W
R77 = R_v2_5: CHIP RES,330ohm,0402 J; Approved: Y; BOM Value: 33/5%/0402; CIS_PART_NUMBER: 20-116-33106-000-RALEC; Manufacturer: RALEC; Manufacturer's Part Number: RTT02331JTP; PART_TYPE: CHIP RES; Package Type: 0402; Part Number: 20-116-33106-000; Tolerance: 5%; W: 1/16W
RN5 = R_PAK_4: BOM Value: 33/8P4R/0402
U8 = TC58DVM82A1TG00: FLASH,NAND,256Mb(32M*8),3.3V,50ns,TC58DVM82A1TG00,TSOP48,TOSHIBA; Approved: Y; BOM Value: 6600-HY27UF08C1; CIS_PART_NUMBER: 08-117-04004-000-TOSHIBA; Index1: VDD=2.7V-3.6V; Index3: 50ns; Manufacturer: TOSHIBA; PART_TYPE: FLASH MEMORY; Part Number: 08-117-04004-000; Size: 32M*8
U14 = AT1202_4_v2
C97 C104 C110 C118 C121 = C: BOM Value: 470P/25V/X5R/0402
C98 = CAP_CERAMIC_0_14: BOM Value: 1U/16V/X5R/0603
C99 = CAP_CERAMIC_0_3: BOM Value: 10U/10V/X5R/0805
C102 = CAP_CERAMIC_0_8: BOM Value: 10U/10V/X5R/0805
C103 = CAP_CERAMIC_0_6: BOM Value: 10U/10V/X5R/0805
C105 = CAP_CERAMIC_0_4: BOM Value: 10U/10V/X5R/0805
C106 = CAP_CERAMIC_0_11: BOM Value: 10U/10V/X5R/0805
C107 C133 = CAP_CERAMIC_0_1: BOM Value: 10U/10V/X5R/0805
C108 = CAP_CERAMIC_0_7: BOM Value: 10U/10V/X5R/0805
C109 = CAP_CERAMIC_0_5: BOM Value: 10U/10V/X5R/0805
C111 = CAP_CERAMIC_0_10: BOM Value: 10U/10V/X5R/0805
C113 = CAP_NP_3: BOM Value: 0.1U/16V/X5R/0402
C114 = CAP_NP_7: CHIP CAP,104PZ/16V,0402,Y5V; Approved: Y; BOM Value: 1000P/25V/X5R/0402; CIS_PART_NUMBER: 24-3E3-10418-000-POE; Manufacturer: POE; Manufacturer's Part Number: B0402F104ZCT; Material: Y5V; PART_TYPE: MLCC; Package Type: 0402; Part Number: 24-3E3-10418-000; Rate Volt: 16V; Tolerance: -20~+80
C115 = CAP_NP_5: CHIP CAP,104PZ/16V,0402,Y5V; Approved: Y; BOM Value: 1000P/25V/X5R/0402; CIS_PART_NUMBER: 24-3E3-10418-000-POE; Manufacturer: POE; Manufacturer's Part Number: B0402F104ZCT; Material: Y5V; PART_TYPE: MLCC; Package Type: 0402; Part Number: 24-3E3-10418-000; Rate Volt: 16V; Tolerance: -20~+80
C116 = CAP_NP_2: CHIP CAP,104PZ/16V,0402,Y5V; Approved: Y; BOM Value: 1000P/25V/X5R/0402; CIS_PART_NUMBER: 24-3E3-10418-000-POE; Manufacturer: POE; Manufacturer's Part Number: B0402F104ZCT; Material: Y5V; PART_TYPE: MLCC; Package Type: 0402; Part Number: 24-3E3-10418-000; Rate Volt: 16V; Tolerance: -20~+80
C117 = CAP_NP_4: CHIP CAP,104PZ/16V,0402,Y5V; Approved: Y; BOM Value: 0.01U/16V/X5R/0402; CIS_PART_NUMBER: 24-3E3-10418-000-POE; Manufacturer: POE; Manufacturer's Part Number: B0402F104ZCT; Material: Y5V; PART_TYPE: MLCC; Package Type: 0402; Part Number: 24-3E3-10418-000; Rate Volt: 16V; Tolerance: -20~+80
C120 = CAP_CERAMIC_0_2: BOM Value: 10U/10V/X5R/0805
C122 = CAP_CERAMIC_0_12: BOM Value: 10U/10V/X5R/0805
C123 = CAP_CERAMIC_0_13: BOM Value: 10U/10V/X5R/0805
C124 = CAP_CERAMIC_0_9: BOM Value: 10U/10V/X5R/0805
C125 = CAP_CERAMIC_0: BOM Value: 10U/10V/X5R/0805
CN8 = SOLDERPAD_0: Vender: ÂEªQ
CT1 = CAPACITOR_POL: BOM Value: 100U/6.3V/20%/TANT-B; PRICE: 0.0619; Vender: Nichicon(·ç´¶)
D16 = DIODE_1
D17 D19 = DIODE_SCHOTTKY_2
L1 = INDUCTOR_0_4
L2 = INDUCTOR_0_5
L3 = INDUCTOR_0_3
L4 = INDUCTOR_0
L5 = INDUCTOR_0_2
L6 = INDUCTOR_0_1
P1 P2 = POINT_0: 8TH PART FIELD: PADR60
Q8 Q9 = MOSFET_N_0
Q10 Q11 Q15 = NPN_0
R78 = R_v2_2: BOM Value: 100K/5%/0402
R79 = R_3: BOM Value: 316K/1%/0402
R80 = R_v2_1: BOM Value: 10K/5%/0402
R81 = R_4: BOM Value: 100K/1%/0402
R82 = R_v2_4: BOM Value: 100K/5%/0402
R83 = R_v2_6: BOM Value: 100K/5%/0402
R84 = R_10: BOM Value: 49.9K/1%/0402
R85 = R_v2: CHIP RES,10K,0402 J; Approved: Y; BOM Value: 0/5%/0402; CIS_PART_NUMBER: 20-116-10306-000-RALEC; Manufacturer: RALEC; Manufacturer's Part Number: RTT02103JTP; PART_TYPE: CHIP RES; Package Type: 0402; Part Number: 20-116-10306-000; Tolerance: 5%; W: 1/16W
R86 = R_12: BOM Value: 100K/1%/0402
R87 = R_8: BOM Value: 124K/1%/0402
R88 = R_9: BOM Value: 100K/1%/0402
R89 = R_v2_3: BOM Value: 220K/5%/0402
R90 = R_11: BOM Value: 50K/5%/0402
R91 = R_2: BOM Value: 70K/5%/0402
R92 = R_6: BOM Value: 50K/5%/0402
R93 = R_1: BOM Value: 5.6K/5%/0402
R94 = R_v2_5: BOM Value: 220K/5%/0402; PRICE: 0.001
R95 = R_5: BOM Value: 274K/1%/0402
R97 = R_v2_7: BOM Value: 10K/1%/0402; PRICE: 0.001
R99 = R_13: BOM Value: 100K/1%/0402
R100 = R_v2_8: BOM Value: 150K/1%/0402; PRICE: 0.001
R101 = R_15: BOM Value: 560K/1%/0402
R102 = R_14: BOM Value: 324K/1%/0402
R103 = R: BOM Value: 100K/1%/0402
R104 = R_7: BOM Value: 2.43/1%/0603
R105 = R_16: BOM Value: 100K/1%/0402
U9 = LOG_74x00_1: PACKAGE: SOT23
U10 = AAT1406_0
U12 = Voltage_Detect_0: Vendor: ELM
C126 = CAP_NP_2: BOM Value: 0.1U/16V/X5R/0402
C127 = CAP_NP_10: BOM Value: 10U/10V/X5R/0805; PRICE: 0.01
C128 = CAP_NP_9: BOM Value: 10U/10V/X5R/0805
C129 = CAPACITOR_FEED_5
C130 = CAP_NP_1: BOM Value: 0.22U/16V/X5R/0603
C131 = CAP_NP_8: BOM Value: 10U/10V/X5R/0805
C132 = CAP_NP: BOM Value: 10U/10V/X5R/0805
C135 = CAP_CERAMIC_0_2
C136 = CAP_CERAMIC_0_3: BOM Value: 1U/16V/X5R/0603
C137 = CAP_NP_4: BOM Value: 8.2P/50V/NPO/0402
C138 = CAP_NP_3: CHIP CAP,105PZ/6.3V,0402,Y5V; Approved: Y; BOM Value: 1U/16V/X5R/0603; CIS_PART_NUMBER: 24-3E3-105G8-000-POE; Manufacturer: POE; Manufacturer's Part Number: K0402F105ZCT; Material: Y5V; PART_TYPE: MLCC; Package Type: 0402; Part Number: 24-3E3-105G8-000; Rate Volt: 6.3V; Tolerance: -20~+80
C139 = CAP_NP_5: BOM Value: 120P/50V/NPO/0402
C140 = CAP_NP_6: BOM Value: 100P/50V/NPO/0402
C141 = CAP_NP_7: BOM Value: 22U/6.3V/X5R/0805
CN9 = CON5_3: Vendor: ¦ãºÍ
L7 = INDUCTOR_0: BOM Value: GLF2012T220K
L8 = SF0905_0: Vender: °ª³Ð
MIC1 = SPEAKER_5: BOM Value: 6633-0000000038
R106 = R_v2_1: CHIP RES,33ohm,0402 J; Approved: Y; BOM Value: 0/5%/0603; CIS_PART_NUMBER: 20-116-33006-000-RALEC; Manufacturer: RALEC; Manufacturer's Part Number: RTT02330JTP; PART_TYPE: CHIP RES; Package Type: 0402; Part Number: 20-116-33006-000; Tolerance: 5%; W: 1/16W
R107 = R_v2_3: BOM Value: 330/5%/0603
R108 = R_v2: BOM Value: 47K/5%/0603
R109 = R_v2_2: BOM Value: 0/5%/0402
R110 = R_v2_8: BOM Value: 330/5%/0603
R112 = R_v2_6: CHIP RES,75ohm,0402 F; Approved: Y; BOM Value: 75/1%/0402; CIS_PART_NUMBER: 20-266-07500-000-RALEC; Manufacturer: RALEC; Manufacturer's Part Number: RTT020750FTP; PART_TYPE: CHIP RES; Package Type: 0402; Part Number: 20-266-07500-000; Tolerance: 1%; W: 1/16W
R113 = R_v2_4: BOM Value: 0/5%/0603
R115 = R_v2_7: CHIP RES,150K,0402 F; Approved: Y; BOM Value: 10K/5%/0402; CIS_PART_NUMBER: 20-266-15030-000-RALEC; Manufacturer: RALEC; Manufacturer's Part Number: RTT021503FTP; PART_TYPE: CHIP RES; Package Type: 0402; Part Number: 20-266-15030-000; Tolerance: 1%; W: 1/16W
R120 = R_v2_5: BOM Value: 0/5%/0402
SP1 = SPEAKER_0: Vendor: ­µ½ç
U13 = WM8978_1: BOM Value: WM8978GEFL

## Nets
DGND: C67.2 C68.2 C69.1 C70.2 C71.2 C72.2 C73.2 C74.2 C77.1 C78.1 C79.1 C80.1 C81.1 C82.1 C83.1 C84.1 C85.1 C86.1 C87.1 C88.1 C89.1 C90.2 C91.1 C93.2 C94.2 C95.1 C96.1 C98.2 C99.2 C101.1 C102.1 C103.1 C105.2 C106.1 C107.1 C108.2 C109.2 C111.2 C112.2 C114.2 C115.2 C116.2 C117.1 C120.2 C122.2 C123.2 C124.2 C125.2 C126.2 C127.2 C128.2 C129.C(GND) C129.D(GND) C130.2 C131.2 C132.1 C133.2 C138.1 C139.2 C140.2 C149.1 CN3.1 CN3.3 CN3.5 CN3.7 CN3.9 CN3.11 CN3.13 CN3.15 CN3.17 CN3.19 CN3.21 CN3.23 CN4.1 CN4.14 CN4.18 CN4.19 CN4.21 CN4.23 CN4.28 CN5.1 CN5.2 CN6.4 CN6.6 CN7.3(VSS) CN7.6(VSS) CN7.11(VSS) CN8.2 CN9.1(GND) CN9.9(GND) CN9.10(GND) CN9.11(GND) CN9.12(GND) CN10.4 CN10.7 CN10.9 CN10.10 CT1.2 D12.A D13.A D14.A D20.A D21.A D22.A D23.A H1.1 H2.1 H3.1 H4.1 H5.1 H6.1 H7.1 H8.1 H9.1 P2.1 Q6.S(SOURCE) Q7.S(SOURCE) Q10.3(GND) Q15.3(GND) Q17.S(SOURCE) R65.1 R70.2 R76.1 R81.2 R85.1 R86.2 R88.2 R99.2 R100.2 R103.2 R104.2 R105.2 R108.2 R109.2 R110.2 R112.2 R115.2 S1.3 S2.3 S3.3 S4.3 SW1.6(COM) TP26.1 TP33.1 TP40.1 U4.2(GND) U5.2(GND) U6.2(GND) U7.A3(VSS) U7.A7(VSSQ) U7.B2(VSSQ) U7.B8(VSSQ) U7.D2(VSSQ) U7.D8(VSSQ) U7.E3(VSS) U7.E7(VSSQ) U7.F2(VSSQ) U7.F8(VSSQ) U7.H2(VSSQ) U7.H8(VSSQ) U7.J3(VSS) U7.J7(VSSDL) U7.N1(VSS) U7.P9(VSS) U8.6(GND) U8.13(VSS) U8.36(VSS) U9.4(GND) U10.11(GND) U10.41(G) U10.42(G) U10.43(G) U10.44(G) U11.2(GND) U12.3(VSS) U13.12(DGND) U13.24(SPKGND) U13.28(AGND) U13.33(CASE) U13.34(GND) U13.35(GND) U13.36(GND) U14.2(GND) U14.5(GND) U15.4(GND) U15.5(DIR) U16.1(GND) ; also on sheet 1 2 3
V18: C77.2 C78.2 C79.2 C80.2 C81.2 C82.2 C83.2 C84.2 C85.2 C86.2 C110.2 C111.1 C123.1 C150.1 CN4.17 L3.2 L5.1 R69.1 R87.1 U7.A1(VDD) U7.A9(VDDQ) U7.C1(VDDQ) U7.C3(VDDQ) U7.C7(VDDQ) U7.C9(VDDQ) U7.E1(VDD) U7.E9(VDDQ) U7.G1(VDDQ) U7.G3(VDDQ) U7.G7(VDDQ) U7.G9(VDDQ) U7.J1(VDDL) U7.J9(VDD) U7.M9(VDD) U7.R1(VDD) U15.1(VCCA) ; also on sheet 1
V28: C68.1 C87.2 CN4.16 U4.5(OUT) U15.8(VCCB) ; also on sheet 3
V30: C67.1 C89.2 C118.2 C120.1 CN3.29 L4.2 R78.2 R95.1 U4.1(VIN) U4.3(CE) U6.1(VIN) U6.3(CE)
V33: C69.2 C88.2 C90.1 C94.1 C95.2 C97.2 C99.1 C129.A(IN) C131.1 CN5.3 CN5.4 CN6.1 CN10.1 CN10.2 L1.2 Q11.2(OUT) R60.2 R61.2 R73.1 R74.1 R75.1 R79.1 R80.1 R82.1 R106.1 R111.1 R125.2 RP1.5 RP1.10 RP2.5 RP2.10 RP3.5 RP3.10 TP27.1 TP32.1 TP39.1 U8.12(VCC) U8.37(VCCQ) U14.4(IN) U14.6(IN) ; also on sheet 1 2 3
V50: C109.1 C133.1 U11.5(OUT) U13.26(SPKVDD) ; also on sheet 2
V53: C121.2 C125.1 D19.C(CATHODE) R102.1 U10.22(ISI5)
VBAT: C119.1 CN8.1 D16.A(ANODE) P1.1 Q9.3(SOURCE) R94.1 R97.1 ; also on sheet 3
VBATT: C98.1 C102.2 C103.2 C106.2 C107.2 C124.1 L6.1 Q8.2(DRAIN) U10.7(VBAT) U10.9(OUT4) U10.26(OUT3) U10.30(OUT2) U10.36(VDD) U10.40(OUT1)
VBATT1: C113.1 CT1.1 D16.C(CATHODE) Q8.3(SOURCE) Q9.2(DRAIN) R89.1 ; also on sheet 2
VDDPWR: C74.1 R83.1 R124.2 U5.1(VCC) U9.8(VCC) U16.2(VIN) ; also on sheet 2
A0: RN2.7 ; also on sheet 1
A1: RN4.3 ; also on sheet 1
A2: RN2.3 ; also on sheet 1
A3: RN1.5 ; also on sheet 1
A4: RN2.5 ; also on sheet 1
A5: RN1.7 ; also on sheet 1
A6: RN4.7 ; also on sheet 1
A7: RN1.1 ; also on sheet 1
A8: RN2.1 ; also on sheet 1
A9: RN1.3 ; also on sheet 1
A10: RN4.1 ; also on sheet 1
A11: RN4.5 ; also on sheet 1
A12: RN3.7 ; also on sheet 1
ADC_KEY: CN6.5 TP36.1 ; also on sheet 3
ADCDAT: U13.9(ADCDAT) ; also on sheet 3
AUDIO-L: C141.1 U13.30(LOUT1)
AV_DET: C138.2 CN9.6(AV_nDET) D20.C R111.2 ; also on sheet 1
BA0: RN3.3 ; also on sheet 1
BA1: RN3.5 ; also on sheet 1
BA2: RN3.1 ; also on sheet 1
BATT_DET: D12.C RP1.7 S1.2 ; also on sheet 3
BCLK: U13.8(BCLK) ; also on sheet 3
CAS#: R68.1 ; also on sheet 1
CK: U7.J8(CK) ; also on sheet 1
CK#: U7.K8(\\~{C}K) ; also on sheet 1
CKE: R63.1 ; also on sheet 1
CMOS_HIS: U15.3(A2) ; also on sheet 3
CMOS_HIS_A: CN4.25 U15.6(B2)
CMOS_PWDN: CN4.30 ; also on sheet 1
CMOS_RST: CN4.29 ; also on sheet 3
CMOS_VIS: U15.2(A1) ; also on sheet 3
CMOS_VIS_A: CN4.24 U15.7(B1)
COMPOSITE: C137.1 C140.1 L7.1 R112.1 ; also on sheet 3
COMS-DSP_CLK: CN4.22 ; also on sheet 3
DACDAT: U13.10(DACDAT) ; also on sheet 3
DACLRC: U13.7(LRC) ; also on sheet 3
DDR_A0: RN2.8 U7.M8(A0)
DDR_A1: RN4.4 U7.M3(A1)
DDR_A2: RN2.4 U7.M7(A2)
DDR_A3: RN1.6 U7.N2(A3)
DDR_A4: RN2.6 U7.N8(A4)
DDR_A5: RN1.8 U7.N3(A5)
DDR_A6: RN4.8 U7.N7(A6)
DDR_A7: RN1.2 U7.P2(A7)
DDR_A8: RN2.2 U7.P8(A8)
DDR_A9: RN1.4 U7.P3(A9)
DDR_A10: RN4.2 U7.M2(A10/AP)
DDR_A11: RN4.6 U7.P7(A11)
DDR_A12: RN3.8 U7.R2(A12)
DDR_BA0: RN3.4 U7.L2(BA0)
DDR_BA1: RN3.6 U7.L3(BA1)
DDR_BA2: RN3.2 U7.L1(NC)
DM0: U7.F3(LDM) ; also on sheet 1
DM1: U7.B3(UDM) ; also on sheet 1
DQ0: U7.G8(DQ0) ; also on sheet 1
DQ1: U7.G2(DQ1) ; also on sheet 1
DQ2: U7.H7(DQ2) ; also on sheet 1
DQ3: U7.H3(DQ3) ; also on sheet 1
DQ4: U7.H1(DQ4) ; also on sheet 1
DQ5: U7.H9(DQ5) ; also on sheet 1
DQ6: U7.F1(DQ6) ; also on sheet 1
DQ7: U7.F9(DQ7) ; also on sheet 1
DQ8: U7.C8(DQ8) ; also on sheet 1
DQ9: U7.C2(DQ9) ; also on sheet 1
DQ10: U7.D7(DQ10) ; also on sheet 1
DQ11: U7.D3(DQ11) ; also on sheet 1
DQ12: U7.D1(DQ12) ; also on sheet 1
DQ13: U7.D9(DQ13) ; also on sheet 1
DQ14: U7.B1(DQ14) ; also on sheet 1
DQ15: U7.B9(DQ15) ; also on sheet 1
DQS0: U7.F7(LDQS) ; also on sheet 1
DQS0#: U7.E8(\\~{LDQ}S) ; also on sheet 1
DQS1: U7.B7(UDQS) ; also on sheet 1
DQS1#: U7.A8(\\~{UDQ}S) ; also on sheet 1
DSP-COMS_CLK: CN4.20 ; also on sheet 3
EO1: R90.1 U10.34(EO1)
EO2: R91.1 U10.32(EO2)
EO5: R92.1 U10.24(EO5)
EO7: R93.1 U10.18(EO7)
I2C_SCK: CN4.27 U13.16(SCLK) ; also on sheet 3
I2C_SDA: CN4.26 U13.17(SDIN) ; also on sheet 3
IN1: C97.1 R79.2 R81.1 U10.3(IN1)
IN2: C104.1 R84.2 R86.1 U10.33(IN2)
IN3: C110.1 R87.2 R88.1 U10.25(IN3)
IN4: C118.1 R95.2 R99.1 U10.12(IN4)
IN5: C121.1 R102.2 R105.1 U10.19(IN5)
IN7H: R101.2 R103.1 U10.16(IN7H)
IR_IN: CN10.6 TP25.1 ; also on sheet 1
ISO5: C108.1 U10.23(ISO5) U11.1(VIN) U11.3(CE)
KEY_DISP: D13.C RP1.6 S2.2 ; also on sheet 1 3
KEY_ENTER: RP2.3 SW1.3(T) ; also on sheet 1
KEY_MENU: D14.C R60.1 S3.2 ; also on sheet 3
KEY_PLAYBACK: CN6.8 RP1.4 TP34.1 ; also on sheet 1
KEY_R1: C73.1 RP2.8 SW1.1(R1) ; also on sheet 3
KEY_R2: C72.1 RP2.6 SW1.2(R2) ; also on sheet 3
KEY_R3: C71.1 RP2.7 SW1.4(R3) ; also on sheet 3
KEY_R4: C70.1 RP2.9 SW1.5(R4) ; also on sheet 3
KEY_REC: CN6.7 RP1.8 TP35.1 ; also on sheet 3
KEY_SHUTTER1: CN5.5 RP1.9 TP28.1 ; also on sheet 1
KEY_SHUTTER2: CN5.6 RP1.1 TP29.1 ; also on sheet 1
KEY_ZOOM_IN: CN5.8 RP1.3 TP31.1 ; also on sheet 1
KEY_ZOOM_OUT: CN5.7 RP1.2 TP30.1 ; also on sheet 1
LCD-ROT-DET: CN3.27 ; also on sheet 1
LCD_EN: CN3.26 ; also on sheet 3
LCD_SCK: CN3.24 ; also on sheet 3
LCD_SDA: CN3.25 ; also on sheet 3
LCDA_CLK: CN3.18 ; also on sheet 1
LCDA_HSYNC: CN3.20 ; also on sheet 1
LCDA_OUT0: CN3.16 ; also on sheet 1
LCDA_OUT1: CN3.14 ; also on sheet 1
LCDA_OUT2: CN3.12 ; also on sheet 1
LCDA_OUT3: CN3.10 ; also on sheet 1
LCDA_OUT4: CN3.8 ; also on sheet 1
LCDA_OUT5: CN3.6 ; also on sheet 1
LCDA_OUT6: CN3.4 ; also on sheet 1
LCDA_OUT7: CN3.2 ; also on sheet 1
LCDA_VSYNC: CN3.22 ; also on sheet 1
LCDBL_CNT: CN3.28 ; also on sheet 1
LCDDET: Q17.D(DRAIN) R125.1 ; also on sheet 1
LCDPOWOFF: C148.2 Q15.1(IN) U16.4(OUT)
LCDV33: C91.2 CN3.30 ; also on sheet 1
LED_BUSY_nCNT: CN6.3 TP38.1 ; also on sheet 3
LED_POWER_nCNT: CN6.2 TP37.1 ; also on sheet 3
LED_SELF: CN10.8 TP24.1 ; also on sheet 3
LOUT2: SP1.1 U13.25(LOUT2)
MACRO_nDET: CN4.15 R61.1 ; also on sheet 1
MCLK: U13.11(MCLK) ; also on sheet 3
MICBIAS: C128.1 R107.1 U13.32(MICBAIC)
MICn: C136.1 U13.2(LIN)
MICp: C134.1 U13.1(LIP)
NAND_CE1: R72.1 ; also on sheet 3
NAND_WP: D15.A(ANODE) R75.2 R76.2 U8.19(~{WP}) ; also on sheet 3
ODT: R64.2 ; also on sheet 1
POWER OFF: Q6.G(GATE) ; also on sheet 1
PWR_DET: Q7.D(DRAIN) R82.2 ; also on sheet 3
PWRENB: Q10.1(IN) U9.2(B2) U9.3(Y2) U10.2(ENI)
RAS#: R67.1 ; also on sheet 1
RESET: D15.C R80.2 U10.20(EN5) U10.31(PGS) ; also on sheet 3
ROUT2: SP1.2 U13.23(ROUT2)
SD0: CN4.13 ; also on sheet 3
SD1: CN4.12 ; also on sheet 3
SD2: CN4.11 ; also on sheet 3
SD3: CN4.10 ; also on sheet 3
SD4: CN4.9 ; also on sheet 3
SD5: CN4.8 ; also on sheet 3
SD6: CN4.7 ; also on sheet 3
SD7: CN4.6 ; also on sheet 3
SD8: CN4.5 ; also on sheet 3
SD9: CN4.4 ; also on sheet 3
SD10: CN4.3 ; also on sheet 3
SD11: CN4.2 ; also on sheet 3
SD_D0: CN7.7(DATA0) RN5.3
SD_D1: CN7.8(DATA1) RN5.7
SD_D2: CN7.9(DATA2) RN5.1
SD_D3: CN7.1(DATA3) RN5.5
SD_POWER_CNT: U14.3(EN) ; also on sheet 1
SMIO0: R74.2 U8.9(~{CE}) ; also on sheet 3
SMIO1: R73.2 U8.7(RY/~{BY}) ; also on sheet 3
SMIO3: CN7.5(SDCLK) ; also on sheet 3
SMIO4: R77.2 RP3.7 ; also on sheet 3
SMIO5: CN7.10(CARD/_IN) RP3.6 ; also on sheet 3
SMIO6: CN7.12(WR/_PROTECT) RP3.9 ; also on sheet 3
SMIO15: U8.8(~{RE}) ; also on sheet 3
SMIO19: U8.18(~{WE}) ; also on sheet 3
SMIO20: U8.17(ALE) ; also on sheet 3
SMIO21: U8.29(I/O1) ; also on sheet 3
SMIO22: U8.30(I/O2) ; also on sheet 3
SMIO23: U8.31(I/O3) ; also on sheet 3
SMIO24: U8.32(I/O4) ; also on sheet 3
SMIO25: U8.41(I/O5) ; also on sheet 3
SMIO26: U8.42(I/O6) ; also on sheet 3
SMIO27: U8.43(I/O7) ; also on sheet 3
SMIO28: U8.44(I/O8) ; also on sheet 3
SMIO29: U8.16(CLE) ; also on sheet 3
SMIO30: RN5.4 RP3.2 ; also on sheet 3
SMIO31: RN5.8 RP3.4 ; also on sheet 3
SMIO32: RN5.2 RP3.1 ; also on sheet 3
SMIO33: RN5.6 RP3.3 ; also on sheet 3
SW1: L1.1 U10.1(SW1)
SW2: L2.1 U10.29(SW2)
SW3: L3.1 U10.27(SW3)
SW4: L4.1 U10.10(SW4)
SW5: D19.A(ANODE) L6.2 U10.21(SW5)
SW7: D17.A(ANODE) L5.2 U10.15(SW7)
USB_DET: Q11.3(GND) R115.1 ; also on sheet 1 3
USBDN: L8.2 ; also on sheet 3
USBDP: L8.3 ; also on sheet 3
USBN: CN9.7(D-) D22.C L8.1
USBP: CN9.5(D+) D23.C L8.4
VD12: C104.2 C105.1 L2.2 R84.1 ; also on sheet 1 3
VD25: U6.5(OUT) ; also on sheet 1 2
VMID: C126.1 C127.1 U13.27(VMID)
VSD33: C96.2 CN7.4(VDD) U14.1(OUT)
VW33: R106.2 U13.13(DCVDD) U13.14(DBVDD)
VWA33: C129.B(OUT) C132.2 U13.31(AVDD)
WE#: R66.1 ; also on sheet 1
WLED_CNT: U10.14(EN7) ; also on sheet 1
WLED_n: CN10.3 R104.1 TP22.1 U10.17(IN7L)
WLED_p: C122.1 CN10.5 D17.C(CATHODE) R101.1 TP23.1
N104012: C112.1 U10.13(VREF)
N16765274: Q6.D(DRAIN) R78.1 U9.1(A2)
N16769257: Q7.G(GATE) Q15.2(OUT) R83.2 S4.2 U9.6(B2)
N16778619: R85.2 U10.6(SEL2)
N16783015: C101.2 U10.37(VNEG)
N16783098: C100.2 U10.39(CP)
N16783105: C100.1 U10.38(CN)
N16783612: TP18.1 U10.28(EN6)
N16783619: TP19.1 U10.4(EO6)
N16783624: TP20.1 U10.5(IN6)
N16783629: TP17.1 U10.35(OUTD)
N16788118: C148.1 Q17.G(GATE) R124.1 U5.3(OUT)
N16788973: C116.1 R92.2
N16788974: C117.2 R93.2
N16788975: C115.1 R91.2
N16805970: C93.1 C150.2 R69.2 R70.1 U7.J2(VREF)
N16860257: U9.5(A2) U9.7(Y2)
N16898736: R64.1 U7.K9(ODT)
N17535128: R72.2 U8.10(NC)
N17719863: CN9.3(AUDIO-L) R113.2
N17719867: C137.2 C139.1 CN9.2(VIDEO) D21.C L7.2
N17720133: C141.2 R113.1
N17757955: C113.2 Q8.1(GATE) Q10.2(OUT) R89.2
N17757956: C119.2 Q9.1(GATE) R94.2 U12.1(VOUT)
N17757971: R97.2 R100.1 U12.2(VIN)
N17811511: CN9.8(VUSB) Q11.1(IN)
N17996068: TP21.1 U13.15(CSB/GPIO1)
N17998912: C130.1 C134.2 C135.2 MIC1.1 R107.2 R108.1
N18002067: R109.1 U13.18(MODE)
N18022102: R65.2 U7.L8(\\~{C}S)
N18089072: C135.1 C136.2 MIC1.2 R110.1
N18107817: C114.1 R90.2
N18202969: R120.2 U13.21(OUT4)
N18202978: R120.1 U13.20(AUXR)
N18571527: C149.2 U16.3(DLY)
N21833759: CN7.2(SDCMD) R77.1
N24788931: R63.2 U7.K2(CKE)
N24790422: R66.2 U7.K3(\\~{W}E)
N24791046: R67.2 U7.K7(\\~{RA}S)
N24791672: R68.2 U7.L7(\\~{CA}S)

Not connected (* = marked no-connect by the designer): CN7 15(DGND) 16(DGND); CN9 4(AUDIO-R)*; RP2 1* 2 4; RP3 8; S1 1* 4*; S2 1* 4* 5 6; S3 1* 4* 5 6; S4 1* 4* 5 6; SW1 7(\) 8(\); U4 4(NC); U6 4(NC); U7 A2(NC)* E2(NC)* R3(NC)* R7(NC)* R8(NC)*; U8 1(NC)* 2(NC)* 3(NC)* 4(NC)* 5(NC)* 11(NC)* 14(NC)* 15(NC)* 20(NC)* 21(NC)* 22(NC)* 23(NC)* 24(NC)* 25(NC)* 26(NC)* 27(NC)* 28(NC)* 33(NC)* 34(NC)* 35(NC)* 38(NC)* 39(NC)* 40(NC)* 45(NC)* 46(NC)* 47(NC)* 48(NC)*; U9 GND VCC; U10 8(SW6); U11 4(NC); U13 3(L2/GPIO2) 4(RIP) 5(RIN) 6(R2/GPIO3) 19(AUXL) 22(OUT3) 29(ROUT1)*

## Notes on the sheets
sheet 4
- CMOSE Interface
sheet 6
- NAND_D7
- NAND_D6
- NAND_R/B
- NAND_D5
- NAND_CE1
- NAND_RE
- NAND_D4
- NAND_CLE
- NAND_ALE
- NAND_D3
- NAND_WE
- NAND_D2
- NAND_WP
- NAND_D1
- NAND_D0
- SD Card Socket  Top View
- SD_CD
- SD_D0
- SD_D1
- 11
- 10
- SD_D2
- SD_D3
- -VSS
- -CARD/ IN
- 8
- 7
- 6
- 5
- 4
- 3
- 2
- 1
- 9
- -DATA1
- -DATA0
- -VSS
- -SDCLK
- -VDD
- -VSS
- -SDCMD
- -DATA3
- -DATA2
- SD_CLK
- SD_WP
- SD_CMD
- 12-WR/PROTECT
- 14
- ¥~´ß±µ¦a
- 13
- SD_D2
- SD_D1
- SD_D0
- SD_WP
- SD_D3
- SD_D3
- SD_D0
- SD_D1
- SD_CMD
- SD_D2
- SD_CD
sheet 7
- PWR : 4AA 4.6V~5V
- CH5:Boost DC-DC converter
